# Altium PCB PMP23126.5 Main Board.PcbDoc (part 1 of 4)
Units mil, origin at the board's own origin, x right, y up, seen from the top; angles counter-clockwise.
Board outline 7480.32 x 4667 mil, 6 copper layers (Top Layer, Signal Layer 1, Signal Layer 2, Signal Layer 3, Signal Layer 4, Bottom Layer), stack 65.8 mil thick; 166 components, 83 nets, 633 pads, 4418 vias.
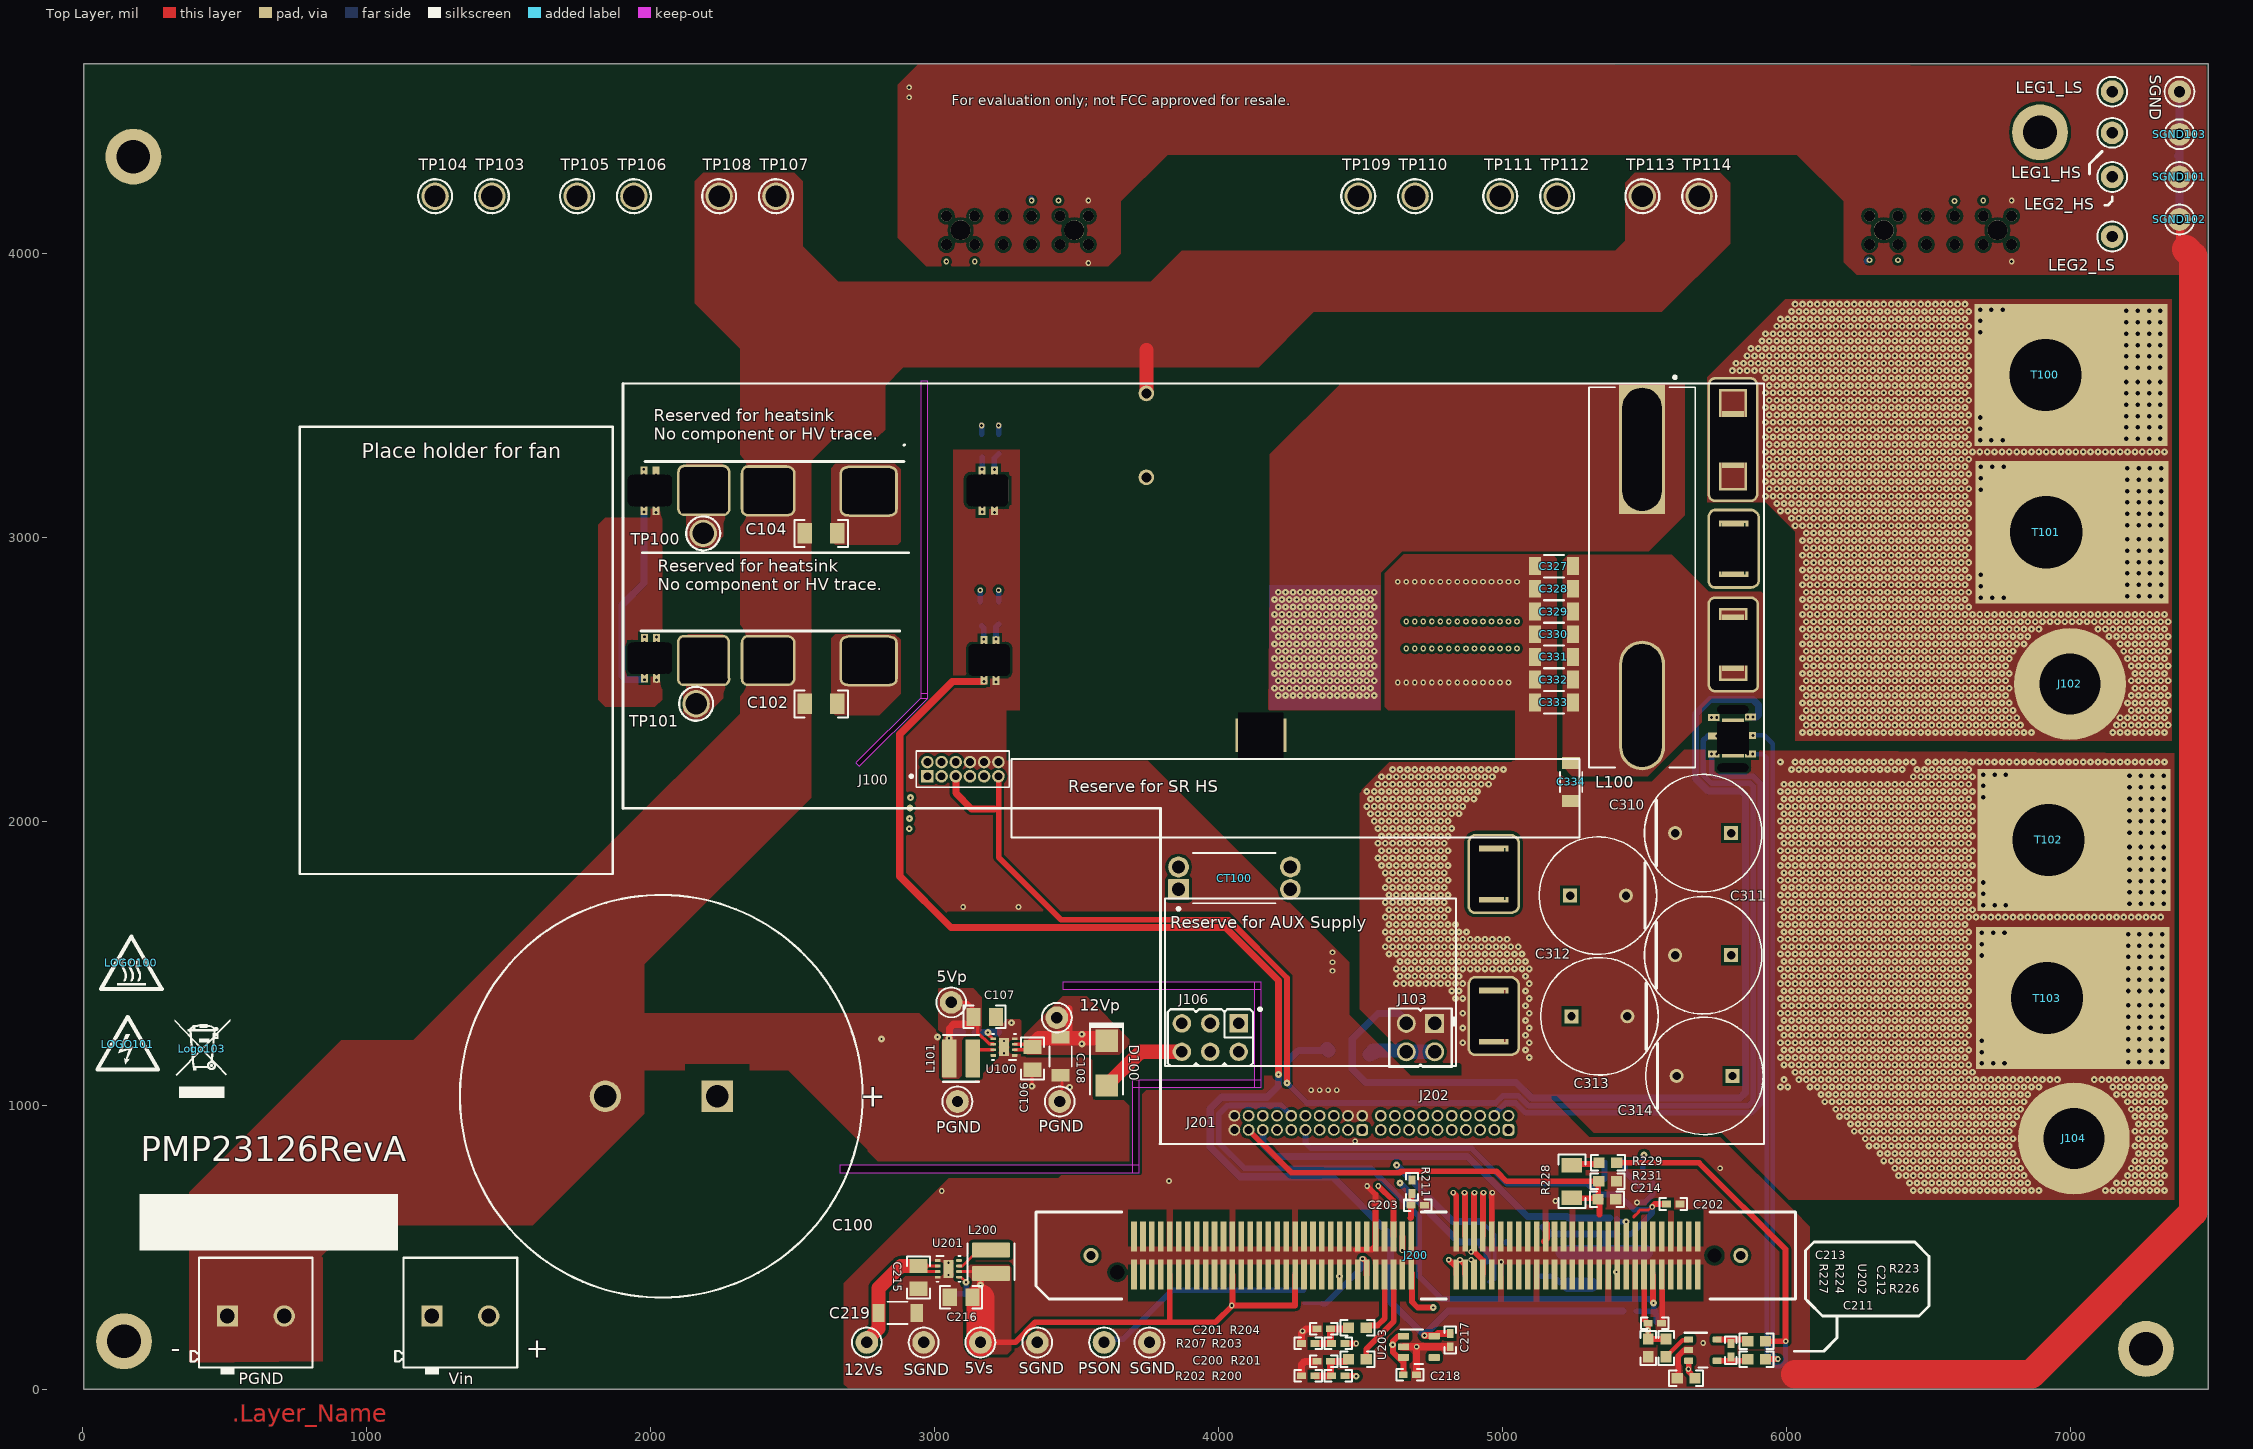
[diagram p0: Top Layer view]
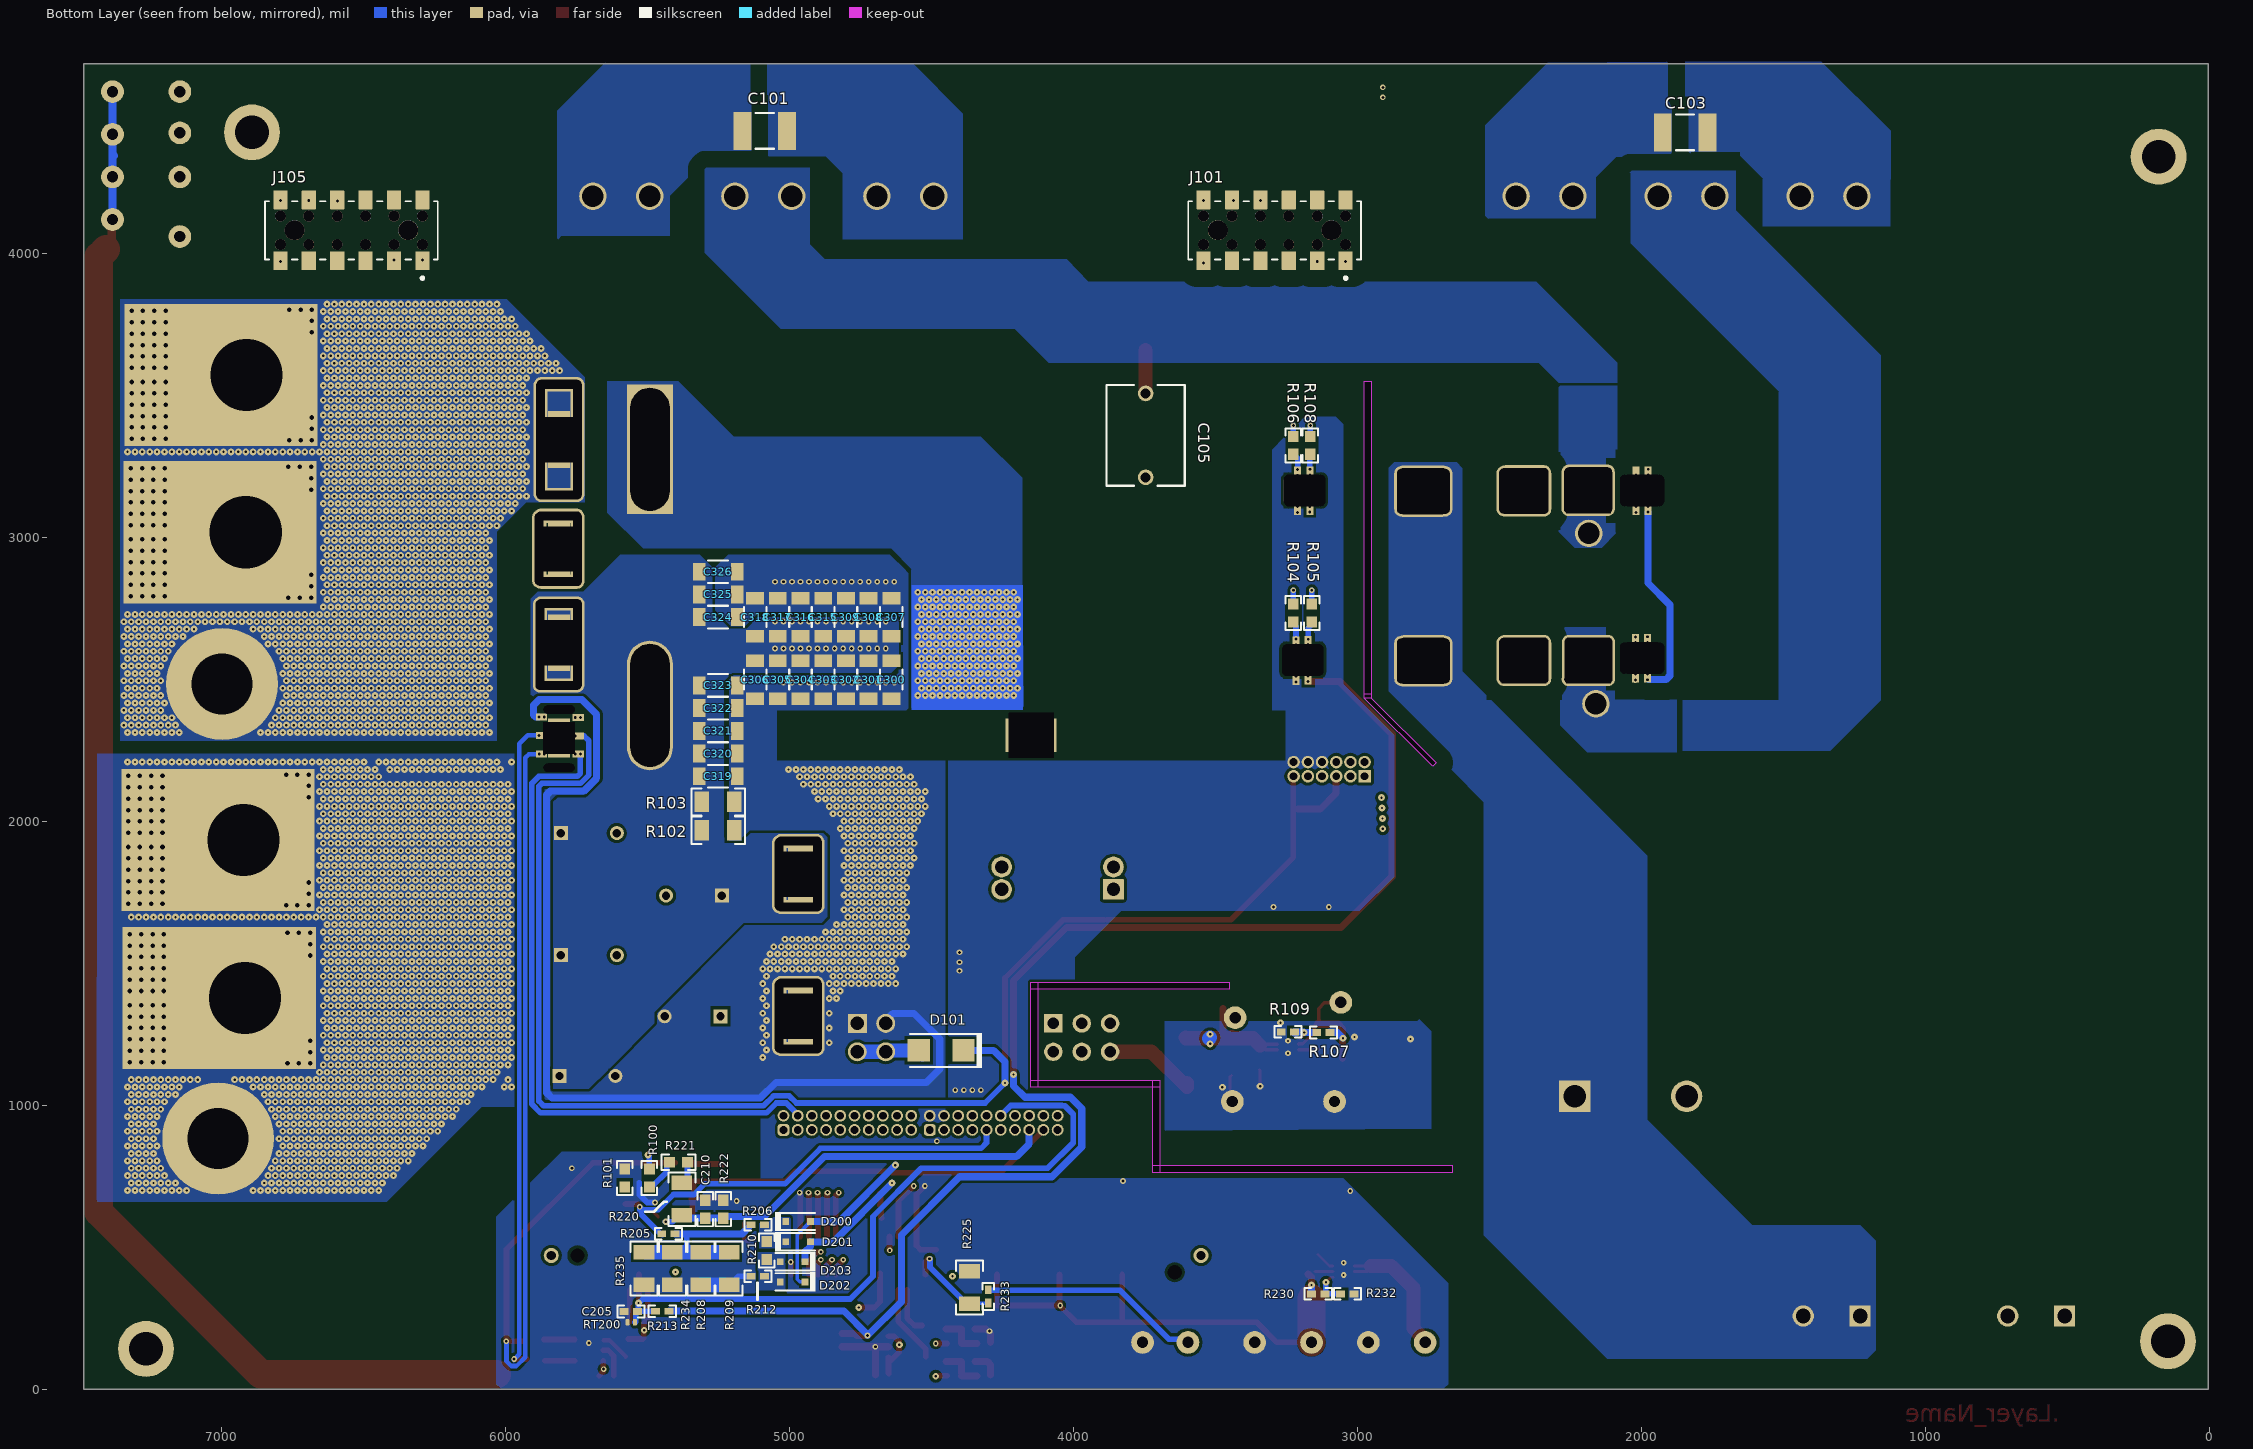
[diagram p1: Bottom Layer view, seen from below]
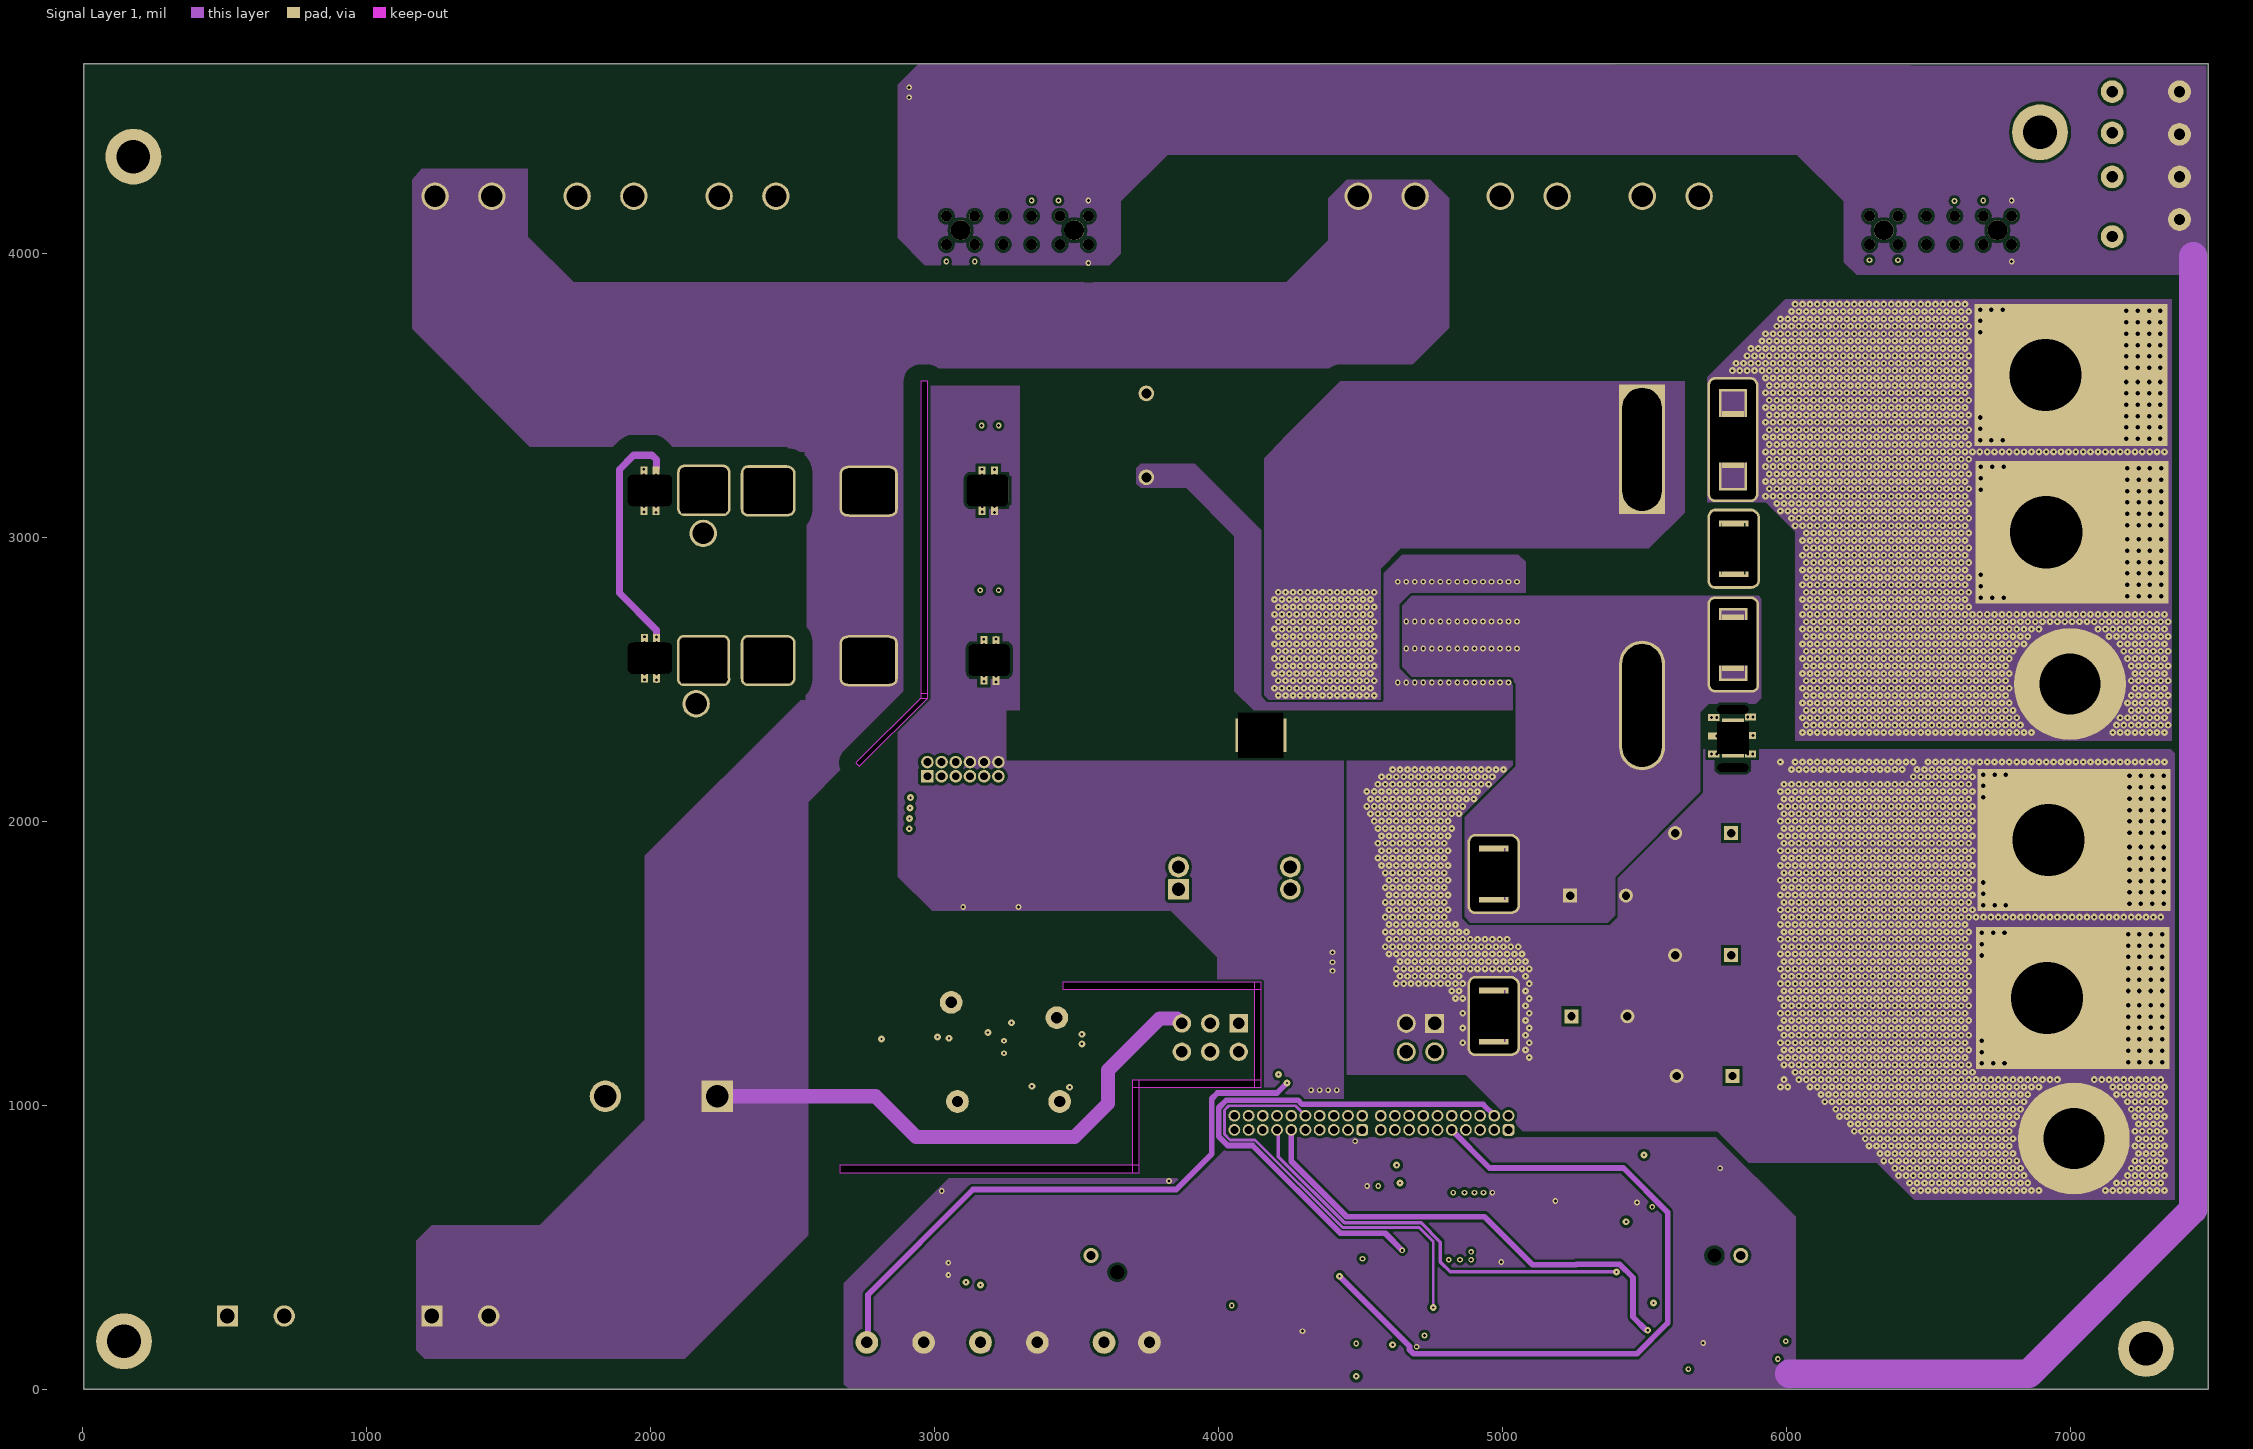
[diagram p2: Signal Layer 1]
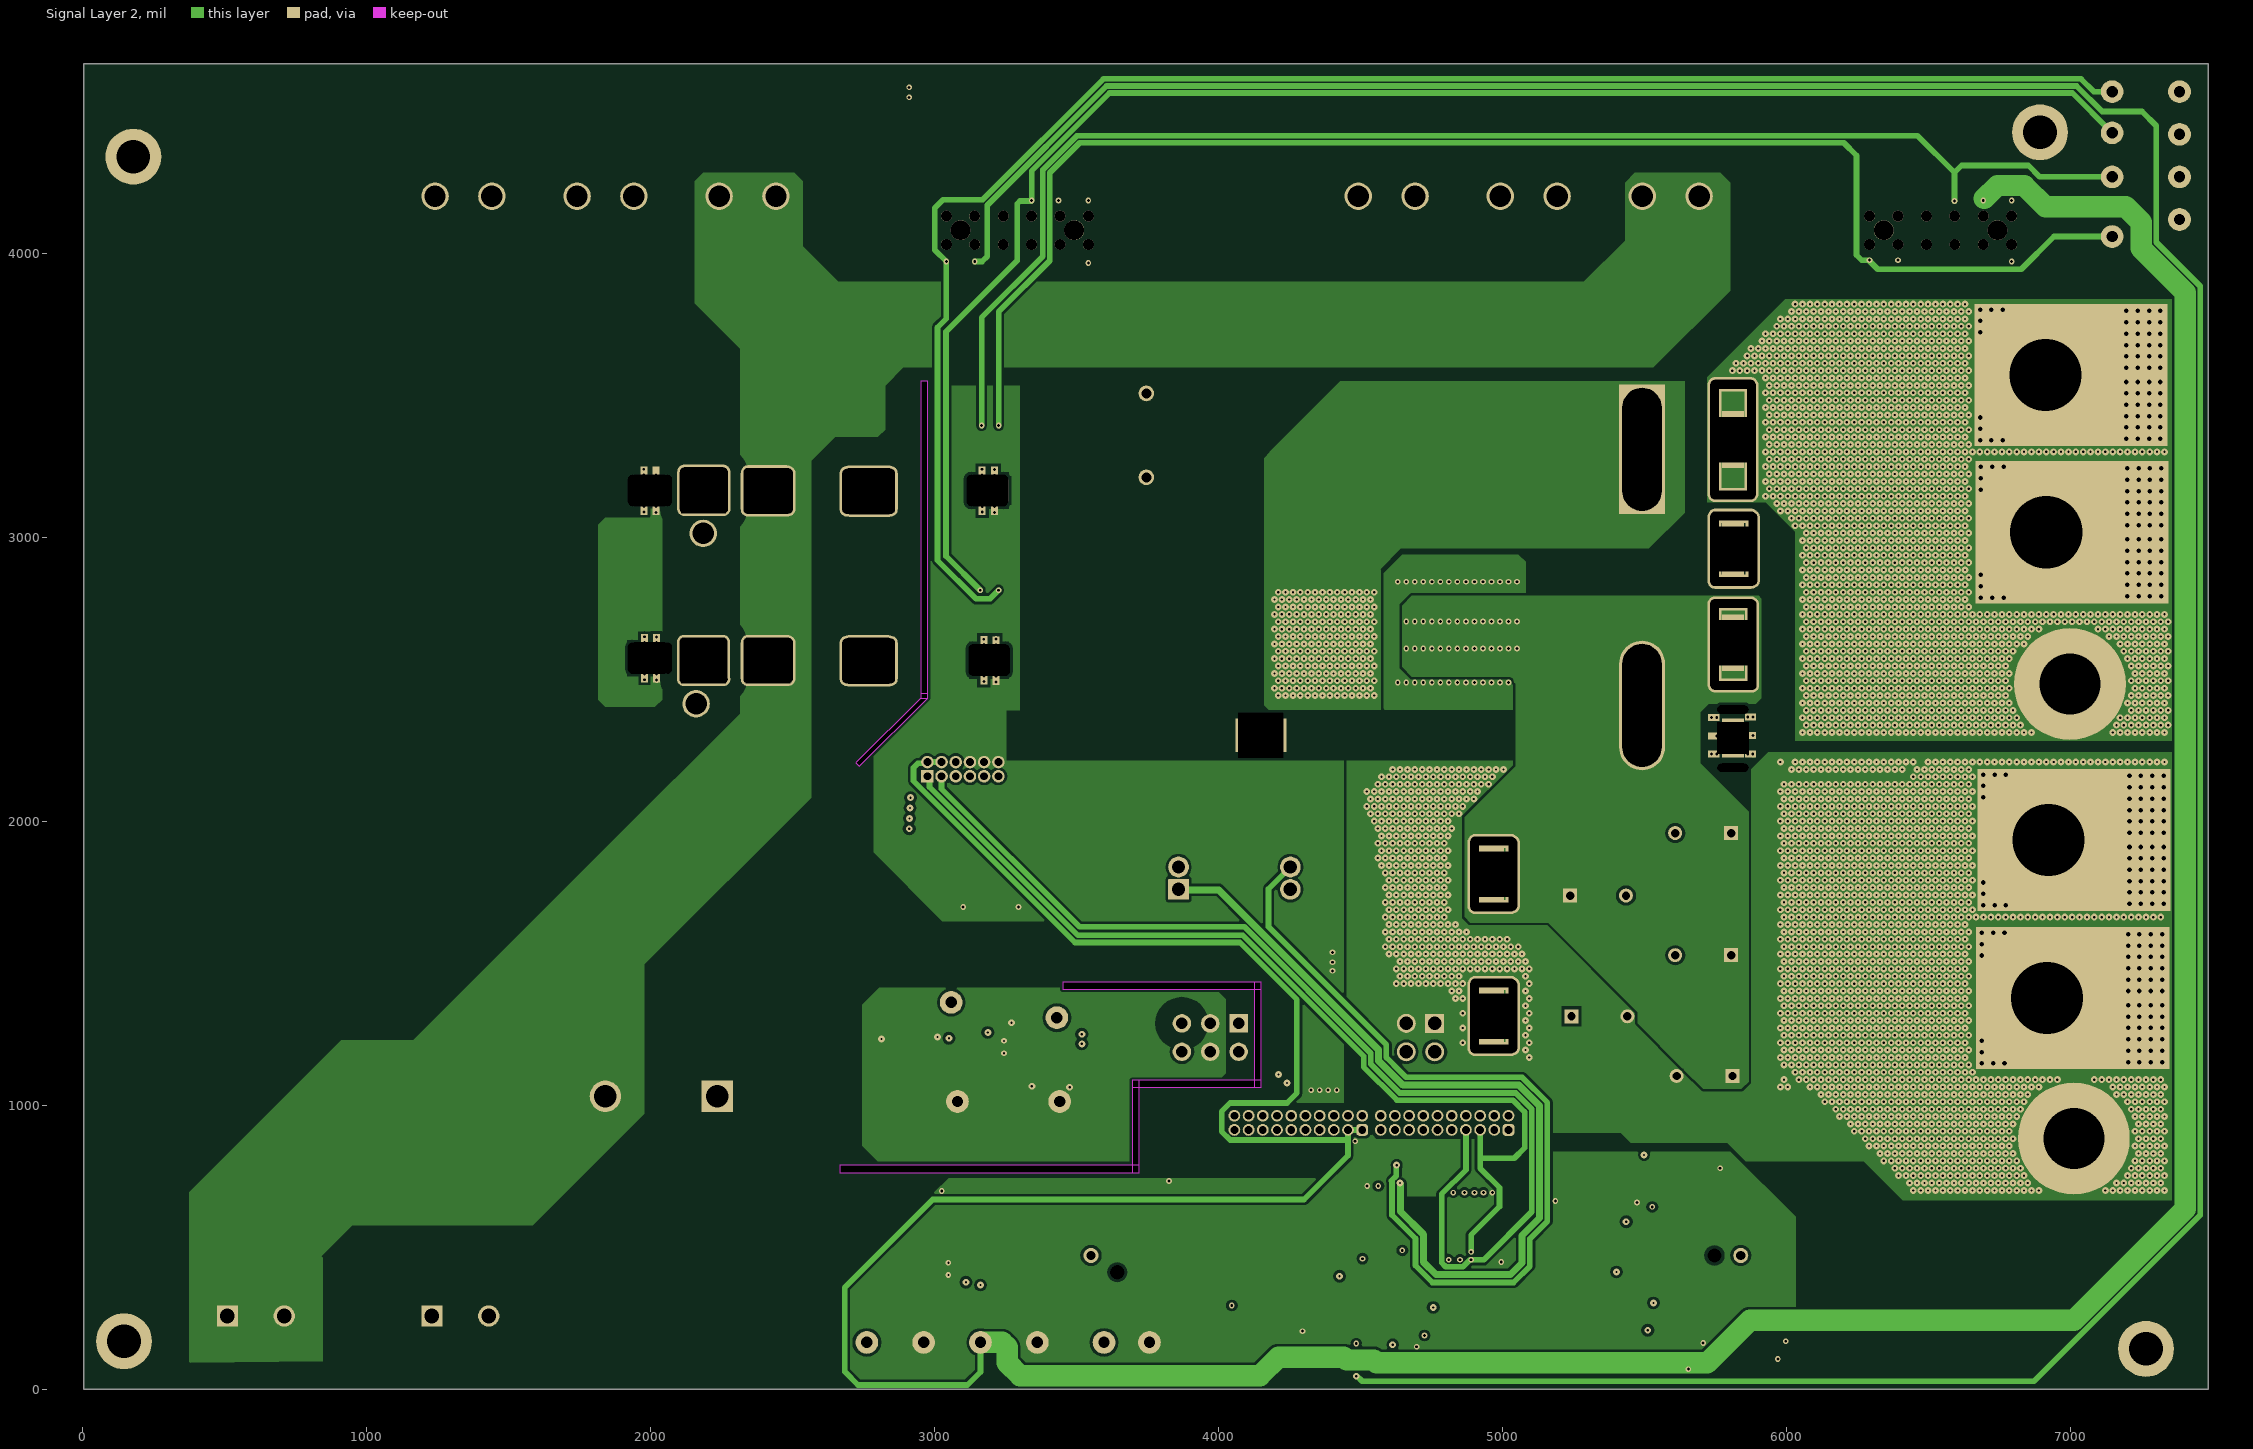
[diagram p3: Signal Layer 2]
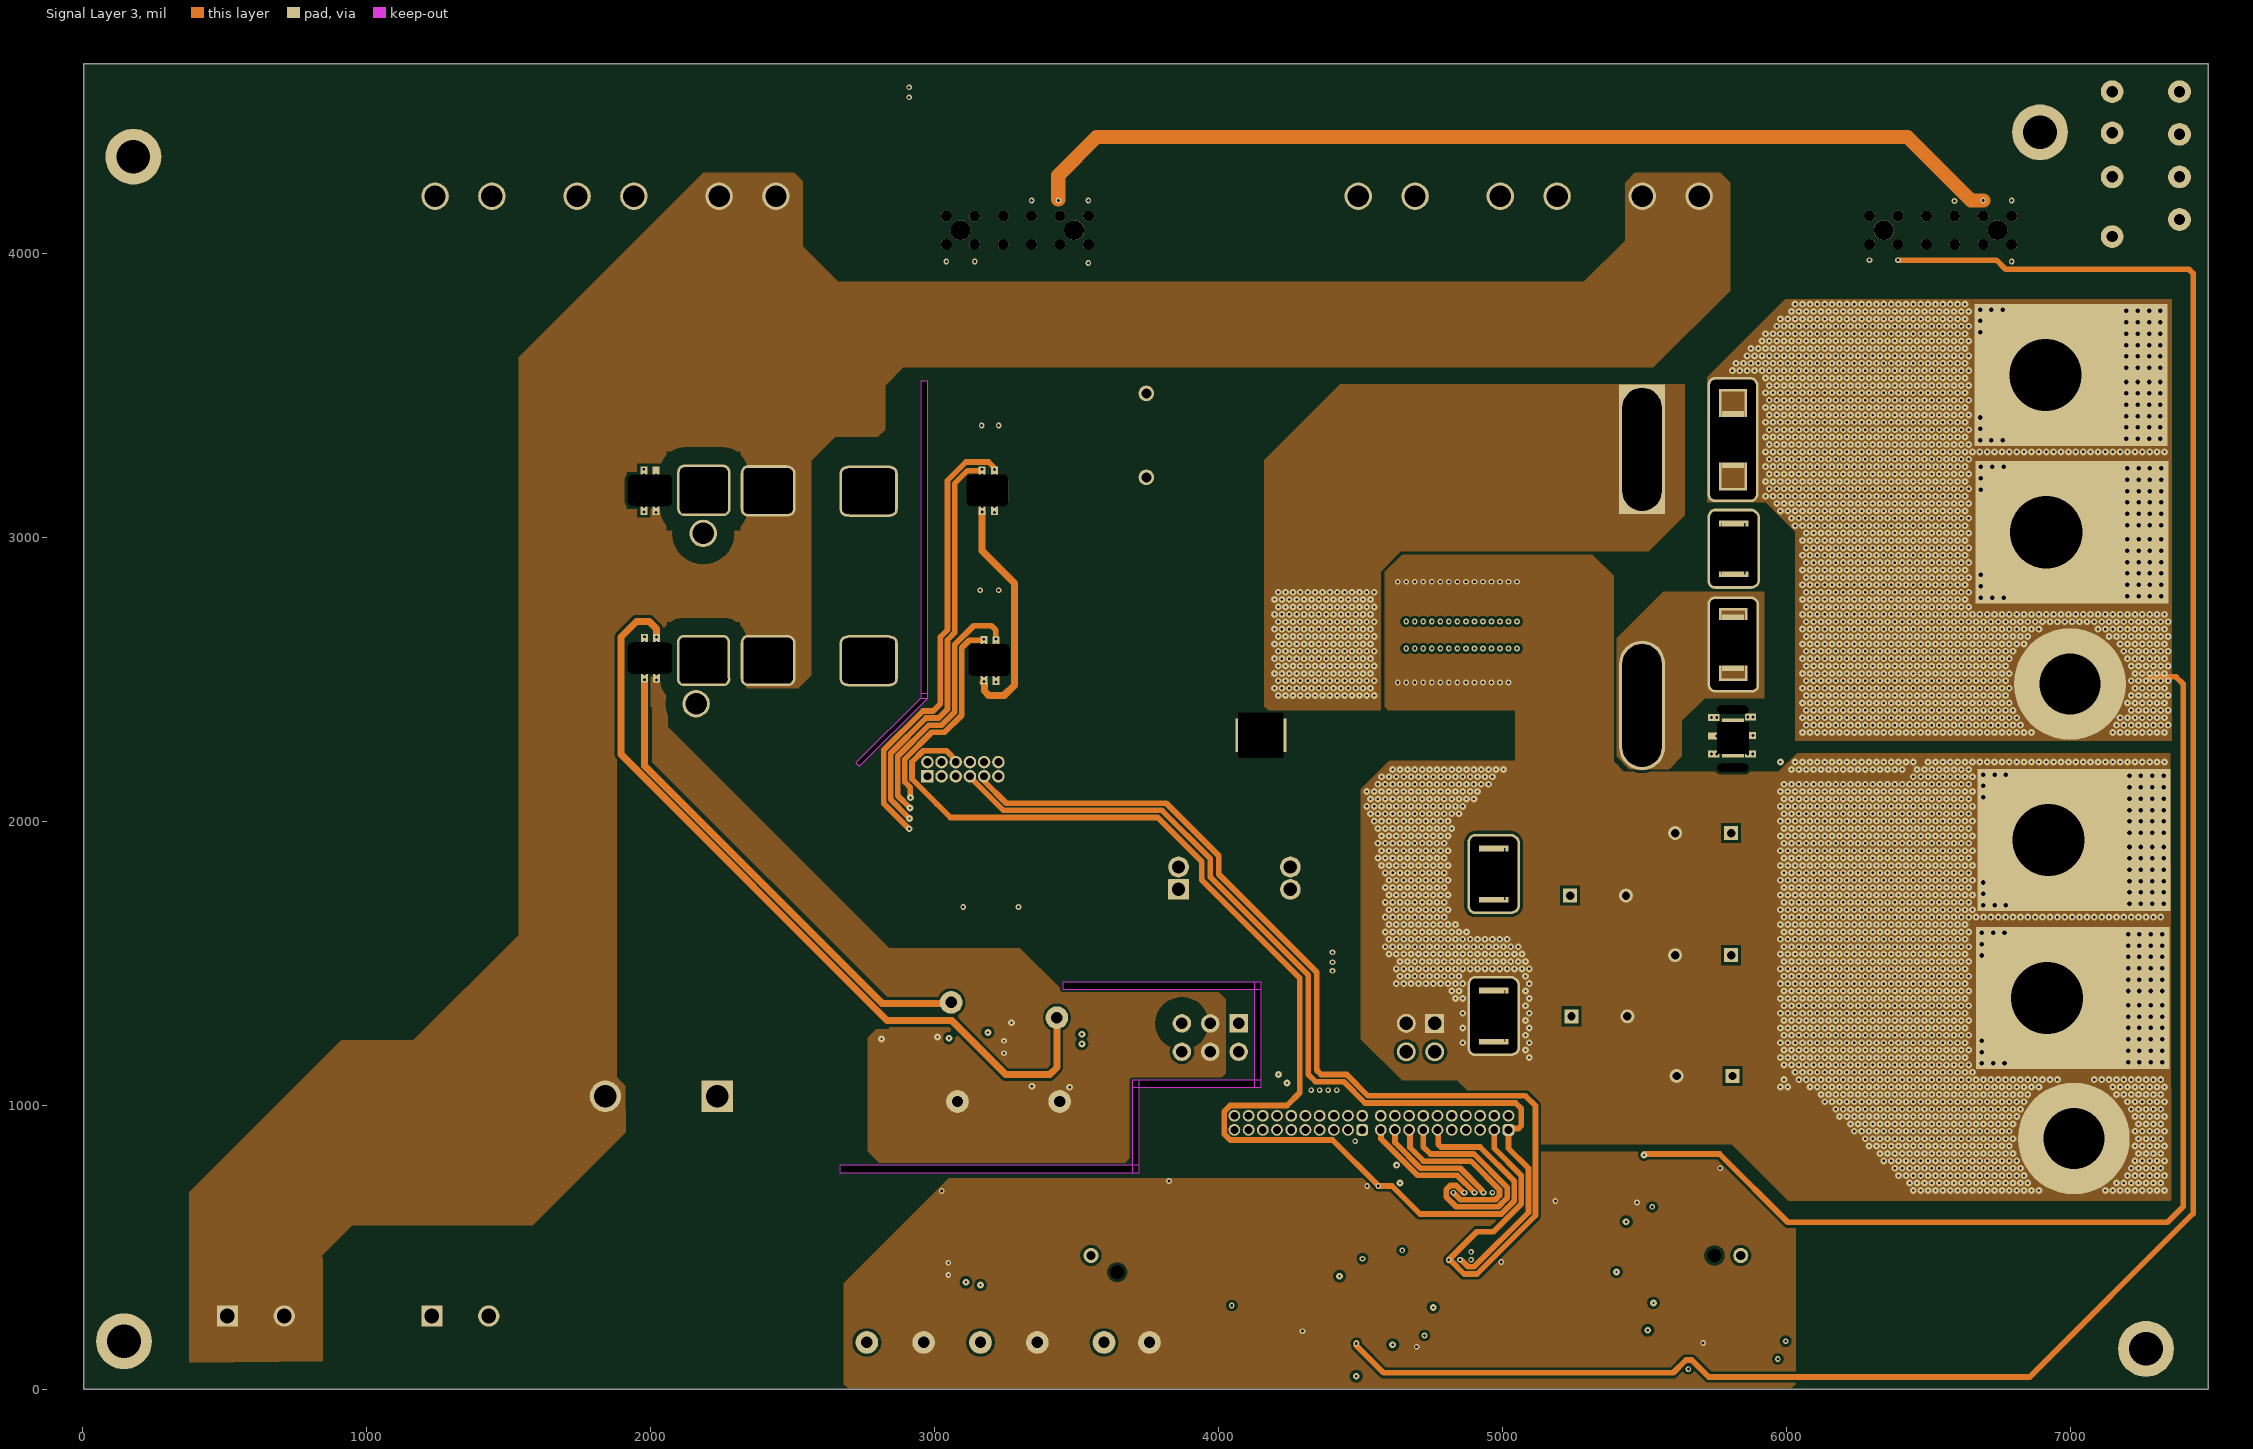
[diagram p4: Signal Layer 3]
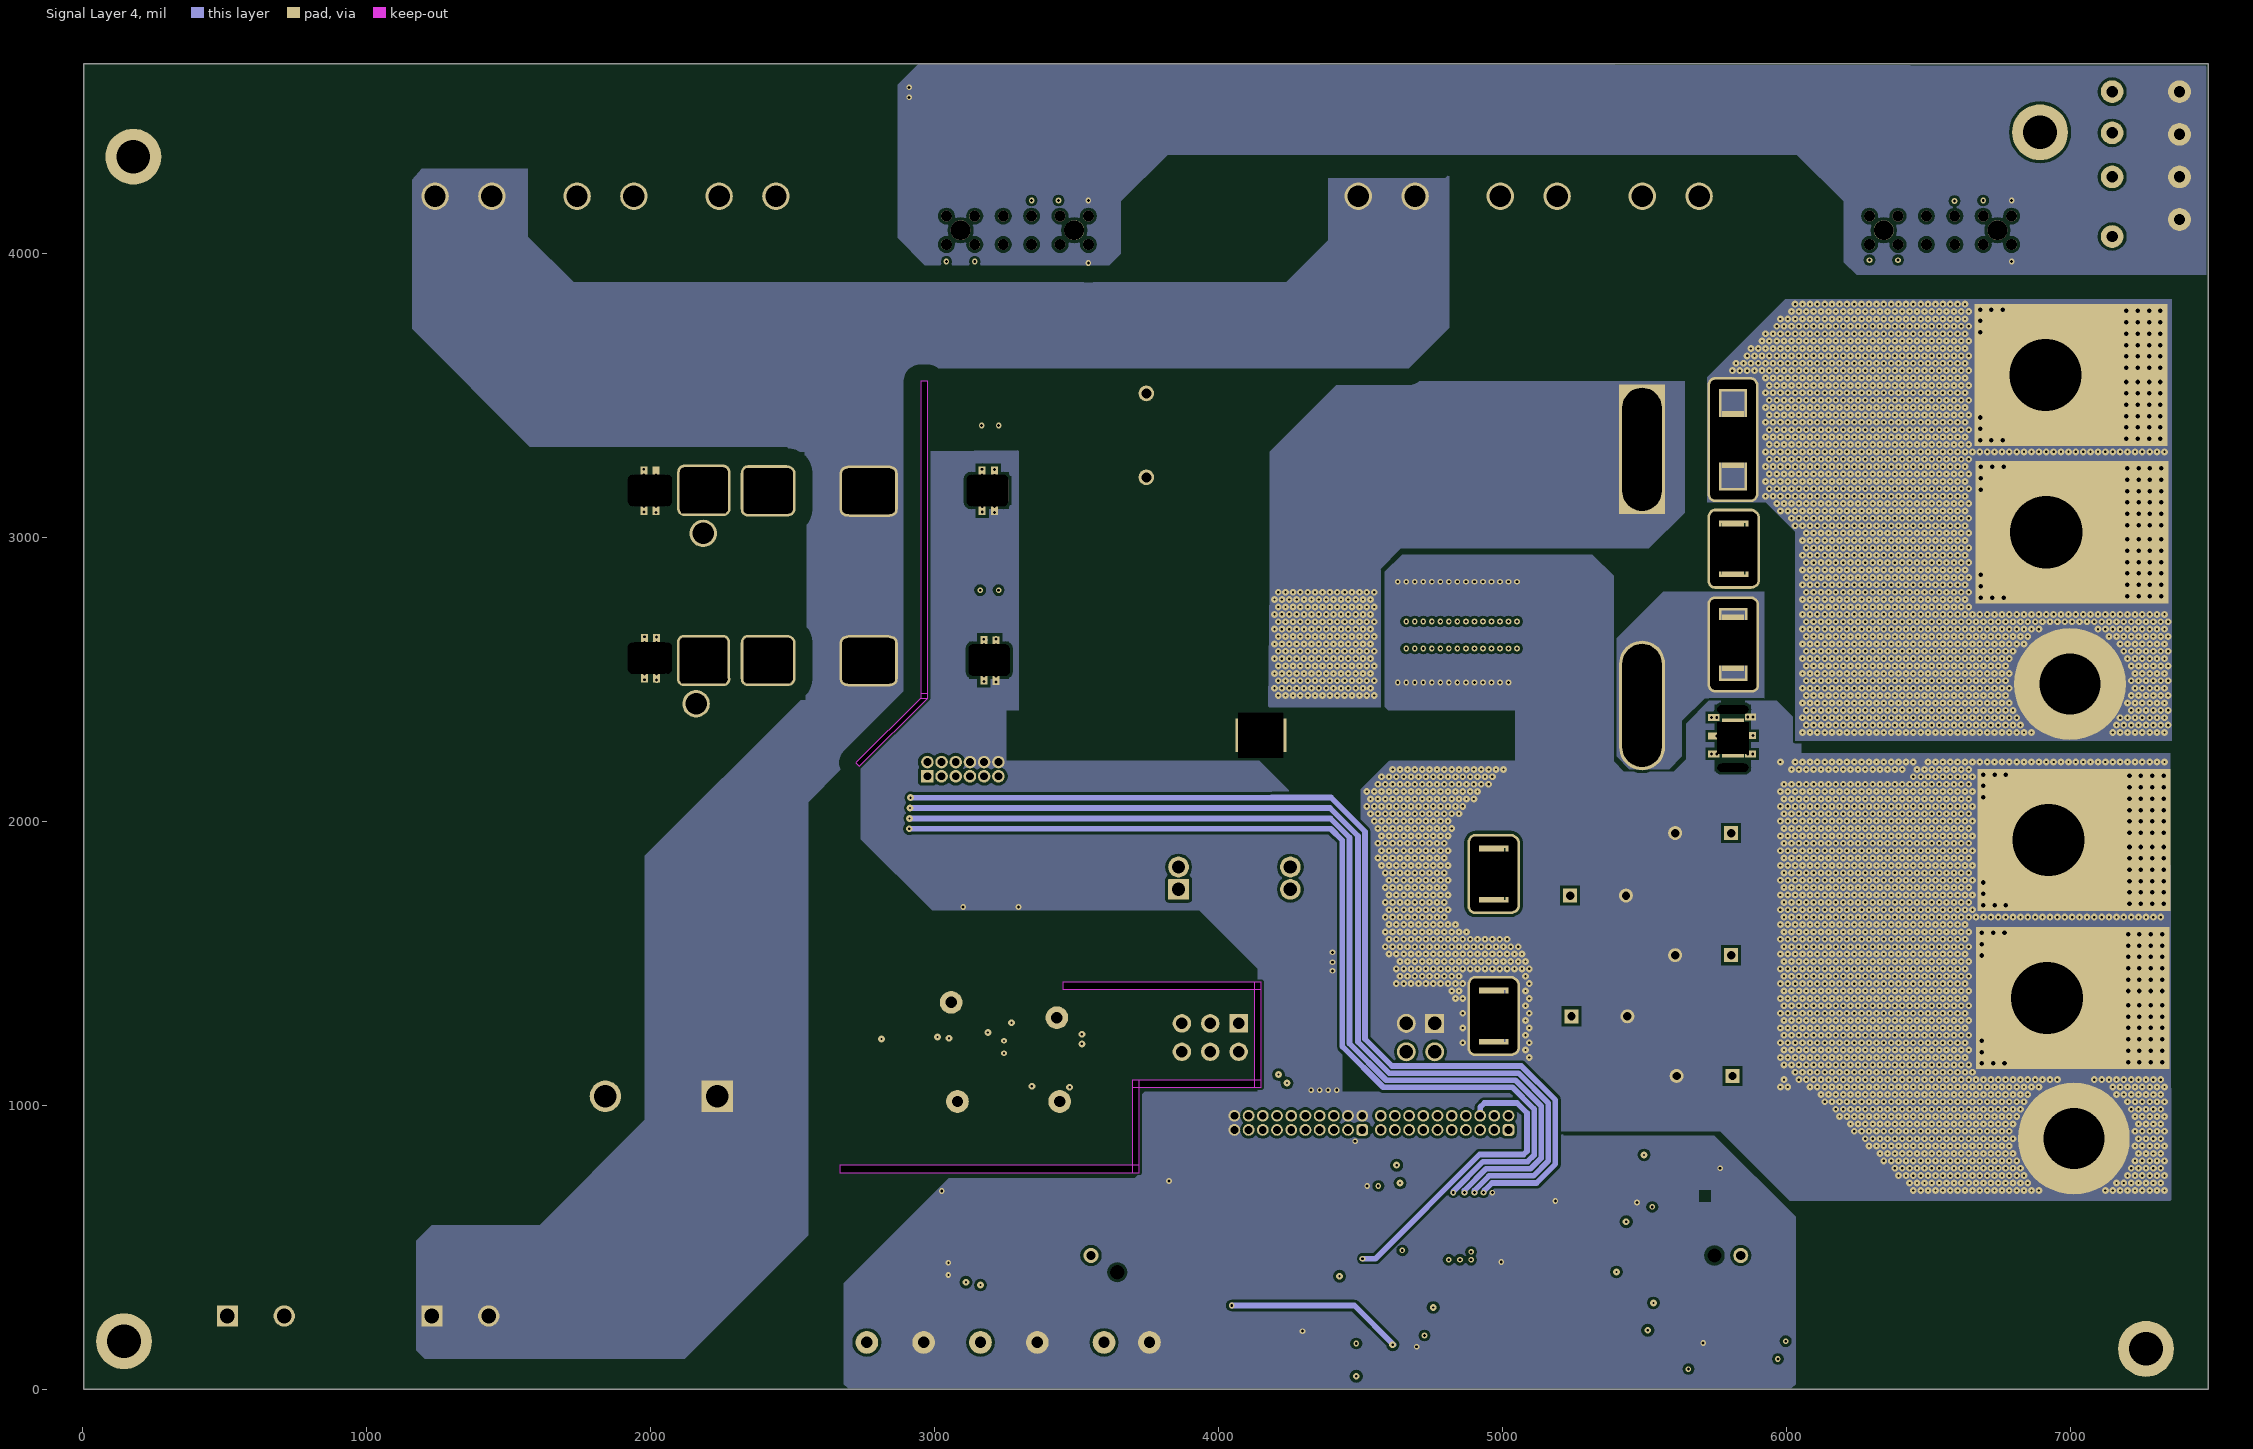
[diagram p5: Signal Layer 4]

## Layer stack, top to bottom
Top Solder: solder mask 0.4, Solder Resist, Dk 3.5
Top Layer: signal copper 2.8
Dielectric 2: prepreg 7, Dk 4.2
Signal Layer 1: signal copper 2.8
Dielectric 3: core 14, Dk 4.2
Signal Layer 2: signal copper 2.8
Dielectric1: prepreg 7, FR-4, Dk 4.2
Signal Layer 3: signal copper 2.8
Dielectric 4: core 14, Dk 4.2
Signal Layer 4: signal copper 2.8
Dielectric 5: prepreg 7, Dk 4.2
Bottom Layer: signal copper 2.8
Bottom Solder: solder mask 0.4, Solder Resist, Dk 3.5

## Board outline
3.6,2 7483.91,2 7483.91,4669 5,4669
cut-out: 4150,1090 3695,1090 3695,1065 4150,1065
cut-out: 3695,1090 3695,765 3720,765 3720,1090
cut-out: 3720,790 2665,790 2665,765 3720,765
cut-out: 4125,1435 4125,1065 4150,1065 4150,1435
cut-out: 4150,1435 3450,1435 3450,1410 4150,1410
cut-out: 2950,2435 2722.5,2207.5 2735,2195 2975,2435 2975,2450 2950,2450
cut-out: 2975,2435 2975,3550 2950,3550 2950,2435

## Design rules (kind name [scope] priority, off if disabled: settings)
AcuteAngle [All] p1: minimum=4.50000000000000E+0001 checktracksonly=FALSE
AssemblyTestPointUsage [All] p1: valid=2
Clearance Clearance_2 [InNetClass('HV') vs Not InNetClass('HV')] p1: gap=60 ignorepadtopadclearanceinfootprint=TRUE except(0: Arc-Hole Track-Hole SMDPad-Hole THPad-Hole Via-Hole Fill-Hole Poly-Hole Region-Hole Text-Hole)
Clearance Clearance_1 [InNetClass('MV') vs Not InNetClass('MV')] p2: gap=40 ignorepadtopadclearanceinfootprint=TRUE
Clearance Clearance_Keepouts [((IsTrack Or IsArc) And Not InPoly) And IsFree and IsKeepOut vs ((IsTrack Or IsArc) And Not InPoly) And IsFree and IsKeepOut] p3: gap=0 ignorepadtopadclearanceinfootprint=FALSE
Clearance Clearance_BoardEdge_MountingHoles [OnCopper and InComponentClass('Mounting Holes') vs IsKeepOut] p4: gap=40 ignorepadtopadclearanceinfootprint=FALSE except(0: Arc-Hole Track-Hole SMDPad-Hole THPad-Hole Via-Hole Fill-Hole Poly-Hole Region-Hole Text-Hole)
Clearance Clearance_BoardEdge_Poly [OnCopper and InPoly vs IsKeepOut] p5: gap=25 ignorepadtopadclearanceinfootprint=FALSE except(0: Arc-Hole Track-Hole SMDPad-Hole THPad-Hole Via-Hole Fill-Hole Poly-Hole Region-Hole Text-Hole)
Clearance Clearance_BoardEdge [OnCopper and Not InComponentClass('Logo') and not InComponentClass('FiducialMark') and not InRegion(1000,500,4000,800) and Not IsKeepout vs IsKeepOut] p6: gap=75 ignorepadtopadclearanceinfootprint=FALSE except(0: Arc-Hole Track-Hole SMDPad-Hole THPad-Hole Via-Hole Fill-Hole Poly-Hole Region-Hole Text-Hole)
Clearance Clearance_Poly [InPolygon] p7: gap=10 ignorepadtopadclearanceinfootprint=FALSE except(0: Arc-Hole Track-Hole SMDPad-Hole THPad-Hole Via-Hole Fill-Hole Poly-Hole Region-Hole Text-Hole)
Clearance [All] p8: gap=7.87 ignorepadtopadclearanceinfootprint=FALSE except(0: Arc-SMDPad Arc-Hole Track-Hole SMDPad-Hole THPad-Hole Via-Hole Fill-Hole Poly-Hole Region-Hole Text-Hole; 5: Arc-Arc Arc-Track Arc-THPad Arc-Via Arc-Fill Track-Track Track-SMDPad Track-THPad Track-Via Track-Fill SMDPad-SMDPad SMDPad-THPad SMDPad-Via SMDPad-Fill THPad-THPad THPad-Via THPad-Fill Via-Via Via-Fill Fill-Fill)
ComponentClearance ComponentClearance_MountingHoles_FiducialMarks [InComponentClass('Mounting Holes') vs InComponentClass('FiducialMark')] p1: gap=20 collisioncheckmode=3 verticalgap=7 showdistances=FALSE
ComponentClearance ComponentClearance_Shunt [InComponentClass('Header') vs InComponentClass('Shunt')] p2: gap=0 collisioncheckmode=3 verticalgap=0 showdistances=FALSE
ComponentClearance ComponentClearance_Logo [InComponentClass('Logo')] p3: gap=5 collisioncheckmode=3 verticalgap=10 showdistances=FALSE
ComponentClearance ComponentClearance_ScrewToNut [(HasFootprint('KEYSTONE_4824')) vs (HasFootprint('Keystone_1903C'))] p4: gap=0 collisioncheckmode=3 verticalgap=0 showdistances=FALSE
ComponentClearance ComponentClearance_MountingHoles [InComponentClass('Mounting Holes')] p5: gap=20 collisioncheckmode=3 verticalgap=7 showdistances=FALSE
ComponentClearance ComponentClearance_SmallPassives [HasFootprint('0201*') or HasFootprint('0402*') or HasFootprint('0508') or HasFootprint('0603*') or HasFootprint('0612') or HasFootprint('0805*') or HasFootprint('0815*') or HasFootprint('0830*') or HasFootprint('1206*') or HasFootprint('1210*') or HasFootprint('1808*') or HasFootprint('1812*') or HasFootprint('1825*') or HasFootprint('2010*') or HasFootprint('2220*') or HasFootprint('2225*') or HasFootprint('2512*') or HasFootprint('2728*') or HasFootprint('3518*') vs HasFootprint('0201*') or HasFootprint('0402*') or HasFootprint('0508') or HasFootprint('0603*') or HasFootprint('0612') or HasFootprint('0805*') or HasFootprint('0815*') or HasFootprint('0830*') or HasFootprint('1206*') or HasFootprint('1210*') or HasFootprint('1808*') or HasFootprint('1812*') or HasFootprint('1825*') or HasFootprint('2010*') or HasFootprint('2220*') or HasFootprint('2225*') or HasFootprint('2512*') or HasFootprint('2728*') or HasFootprint('3518*')] p6: gap=5 collisioncheckmode=3 verticalgap=1 showdistances=FALSE
ComponentClearance ComponentClearance_THtoSMT [IsThruComponent vs IsSMTComponent] p7: gap=10 collisioncheckmode=3 verticalgap=7 showdistances=FALSE
ComponentClearance ComponentClearance_THtoTH [IsThruComponent vs IsThruComponent] p8: gap=10 collisioncheckmode=3 verticalgap=7 showdistances=FALSE
ComponentClearance [All] p9: gap=10 collisioncheckmode=3 verticalgap=7 showdistances=FALSE
DiffPairsRouting [All] p1: maxlimit=100 minlimit=10 mostfreqgap=10 toplayer_minwidth=15 toplayer_maxwidth=15 toplayer_prefwidth=15 midlayer1_minwidth=15 midlayer1_maxwidth=15 midlayer1_prefwidth=15 midlayer2_minwidth=15 midlayer2_maxwidth=15 midlayer2_prefwidth=15 midlayer3_minwidth=15 midlayer3_maxwidth=15 midlayer3_prefwidth=15 midlayer4_minwidth=15 midlayer4_maxwidth=15 midlayer4_prefwidth=15 bottomlayer_minwidth=15 bottomlayer_maxwidth=15 bottomlayer_prefwidth=15 maxuncoupledlength=1000
FabricationTestPointUsage TestPointUsage [All] p1: valid=2 allowmultiple=FALSE
FabricationTestpoint Testpoint [All] p1: side=3 testpointundercomponent=TRUE minsize=40 maxsize=100 preferedsize=60 minholesize=0 maxholesize=40 preferedholesize=32 testpointgrid=1 allowsidetop=TRUE allowsidebottom=TRUE usegrid=TRUE gridtolerance=0.01
FanoutControl Fanout_LCC [IsLCC] p1: bgadir=Out bgaviamode=Centered fanoutstyle=Auto fanoutdirection=Alternating viagrid=1 // Fanout_LCC (Default Rule)
FanoutControl Fanout_BGA [IsBGA] p2: bgadir=Out bgaviamode=Centered fanoutstyle=Auto fanoutdirection=Alternating viagrid=1 // Fanout_BGA (Default Rule)
FanoutControl Fanout_Default [All] p4: bgadir=Out bgaviamode=Centered fanoutstyle=Auto fanoutdirection=Alternating viagrid=1 // Fanout_Default (Default Rule)
FanoutControl Fanout_Small [(CompPinCount < 5)] p5: bgadir=Out bgaviamode=Centered fanoutstyle=Auto fanoutdirection=OutThenIn viagrid=1 // Fanout_Small (Default Rule)
Height [All] p1: minheight=0 maxheight=3000 prefheight=500
HoleSize [All] p1: absolutevalues=TRUE maxlimit=501 minlimit=7 maxpercent=80.000 minpercent=20.000
MinimumAnnularRing MinimumAnnularRing_ThermalPadVias [IsVia and InAnyComponent] p1: minimumring=5.91
MinimumAnnularRing [All] p2: minimumring=5
MinimumSolderMaskSliver MinimumSolderMaskSliver_Logo [InComponentClass('Logo') vs InComponentClass('Logo')] p1: minsoldermaskwidth=0.7
MinimumSolderMaskSliver [All] p2: minsoldermaskwidth=0.7
PlaneConnect [All] p1: planeconnectstyle=Direct reliefexpansion=10 reliefentries=4 reliefconductorwidth=10 reliefairgap=10
PolygonConnect PolygonConnect_16 [All vs IsNamedPolygon('C106_2') Or  IsNamedPolygon('Vout') Or  IsNamedPolygon('IN+') Or  IsNamedPolygon('Q203_5') Or  IsNamedPolygon('IN+') Or  IsNamedPolygon('Q201_5') Or  IsNamedPolygon('C108_2') Or  IsNamedPolygon('SGND') Or  IsNamedPolygon('IN+') Or  IsNamedPolygon('SGND') Or  IsNamedPolygon('Q203_5') Or  IsNamedPolygon('IN+') Or  IsNamedPolygon('SGND') Or  IsNamedPolygon('GND') Or  IsNamedPolygon('C113_2') Or  IsNamedPolygon('C107_2') Or  IsNamedPolygon('C107_2') Or  IsNamedPolygon('Vout') Or  IsNamedPolygon('SIGNAL_LAYER_1_GND_P074') Or  IsNamedPolygon('HV') Or  IsNamedPolygon('C108_2') Or  IsNamedPolygon('C103_2') Or  IsNamedPolygon('Q201_5') Or  IsNamedPolygon('Vout') Or  IsNamedPolygon('C109_2') Or  IsNamedPolygon('Q201_5') Or  IsNamedPolygon('GND') Or  IsNamedPolygon('C107_2') Or  IsNamedPolygon('C102_1') Or  IsNamedPolygon('GND') Or  IsNamedPolygon('SGND') Or  IsNamedPolygon('HS') Or  IsNamedPolygon('Q203_5') Or  IsNamedPolygon('Q201_5') Or  IsNamedPolygon('Q203_5')] p1: connectstyle=Direct reliefconductorwidth=10 reliefentries=4 polygonreliefangle="90 Angle" airgapwidth=10
PolygonConnect PolygonConnect_15 [All vs IsNamedPolygon('C109_2') Or  IsNamedPolygon('C107_2') Or  IsNamedPolygon('HV') Or  IsNamedPolygon('Q203_5') Or  IsNamedPolygon('C107_2') Or  IsNamedPolygon('HS') Or  IsNamedPolygon('Q201_5') Or  IsNamedPolygon('Q203_5') Or  IsNamedPolygon('C106_2') Or  IsNamedPolygon('C108_2') Or  IsNamedPolygon('Vout') Or  IsNamedPolygon('Q203_5') Or  IsNamedPolygon('C108_2') Or  IsNamedPolygon('C113_2') Or  IsNamedPolygon('Q203_5') Or  IsNamedPolygon('Q201_5') Or  IsNamedPolygon('C107_2') Or  IsNamedPolygon('C102_1') Or  IsNamedPolygon('SGND') Or  IsNamedPolygon('GND') Or  IsNamedPolygon('SGND') Or  IsNamedPolygon('GND') Or  IsNamedPolygon('IN+') Or  IsNamedPolygon('IN+') Or  IsNamedPolygon('Q201_5') Or  IsNamedPolygon('Q201_5') Or  IsNamedPolygon('SGND') Or  IsNamedPolygon('SGND') Or  IsNamedPolygon('Vout') Or  IsNamedPolygon('Vout') Or  IsNamedPolygon('IN+') Or  IsNamedPolygon('GND') Or  IsNamedPolygon('IN+') Or  IsNamedPolygon('GND')] p2: connectstyle=Direct reliefconductorwidth=10 reliefentries=4 polygonreliefangle="90 Angle" airgapwidth=10
PolygonConnect PolygonConnect_14 [All vs IsNamedPolygon('C106_2') Or  IsNamedPolygon('C107_2') Or  IsNamedPolygon('C107_2') Or  IsNamedPolygon('C107_2') Or  IsNamedPolygon('C102_1') Or  IsNamedPolygon('Q203_5') Or  IsNamedPolygon('Vout') Or  IsNamedPolygon('Q203_5') Or  IsNamedPolygon('Q203_5') Or  IsNamedPolygon('Q201_5') Or  IsNamedPolygon('C108_2') Or  IsNamedPolygon('Q203_5') Or  IsNamedPolygon('HS') Or  IsNamedPolygon('HV') Or  IsNamedPolygon('C108_2') Or  IsNamedPolygon('Q201_5') Or  IsNamedPolygon('C109_2') Or  IsNamedPolygon('Q201_5') Or  IsNamedPolygon('Q201_5') Or  IsNamedPolygon('C113_2')] p3: connectstyle=Direct reliefconductorwidth=10 reliefentries=4 polygonreliefangle="90 Angle" airgapwidth=10
PolygonConnect PolygonConnect_13 [All vs IsNamedPolygon('C102_1') Or  IsNamedPolygon('HV') Or  IsNamedPolygon('C107_2') Or  IsNamedPolygon('C109_2') Or  IsNamedPolygon('C107_2') Or  IsNamedPolygon('C108_2') Or  IsNamedPolygon('C106_2') Or  IsNamedPolygon('C108_2') Or  IsNamedPolygon('C113_2') Or  IsNamedPolygon('C107_2')] p4: connectstyle=Direct reliefconductorwidth=10 reliefentries=4 polygonreliefangle="90 Angle" airgapwidth=10
PolygonConnect PolygonConnect_12 [All vs IsNamedPolygon('C107_2') Or  IsNamedPolygon('C113_2') Or  IsNamedPolygon('C106_2') Or  IsNamedPolygon('C107_2') Or  IsNamedPolygon('C107_2') Or  IsNamedPolygon('C102_1')] p5: connectstyle=Direct reliefconductorwidth=10 reliefentries=4 polygonreliefangle="90 Angle" airgapwidth=10
PolygonConnect PolygonConnect_11 [All vs IsNamedPolygon('C106_2') Or  IsNamedPolygon('C102_1') Or  IsNamedPolygon('C107_2') Or  IsNamedPolygon('C107_2') Or  IsNamedPolygon('C107_2')] p6: connectstyle=Direct reliefconductorwidth=10 reliefentries=4 polygonreliefangle="90 Angle" airgapwidth=10
PolygonConnect PolygonConnect_10 [All vs IsNamedPolygon('C106_2')] p7: connectstyle=Direct reliefconductorwidth=10 reliefentries=4 polygonreliefangle="90 Angle" airgapwidth=10
PolygonConnect PolygonConnect_9 [All vs IsNamedPolygon('C11_1') Or  IsNamedPolygon('Vin') Or  IsNamedPolygon('Vin') Or  IsNamedPolygon('5V') Or  IsNamedPolygon('D6_2') Or  IsNamedPolygon('Q3_3') Or  IsNamedPolygon('GND2') Or  IsNamedPolygon('GND2') Or  IsNamedPolygon('GND') Or  IsNamedPolygon('Q3_4') Or  IsNamedPolygon('12V5') Or  IsNamedPolygon('GND') Or  IsNamedPolygon('12V5') Or  IsNamedPolygon('D3_1')] p8: connectstyle=Direct reliefconductorwidth=10 reliefentries=4 polygonreliefangle="90 Angle" airgapwidth=10
PolygonConnect PolygonConnect_8 [All vs IsNamedPolygon('C11_1') Or  IsNamedPolygon('Vin') Or  IsNamedPolygon('12V5') Or  IsNamedPolygon('Q3_3') Or  IsNamedPolygon('GND2') Or  IsNamedPolygon('GND2') Or  IsNamedPolygon('5V') Or  IsNamedPolygon('Q3_4') Or  IsNamedPolygon('12V5')] p9: connectstyle=Direct reliefconductorwidth=10 reliefentries=4 polygonreliefangle="90 Angle" airgapwidth=10
PolygonConnect PolygonConnect_7 [All vs IsNamedPolygon('GND2') Or  IsNamedPolygon('GND2') Or  IsNamedPolygon('5V') Or  IsNamedPolygon('12V5') Or  IsNamedPolygon('12V5') Or  IsNamedPolygon('C11_1')] p10: connectstyle=Direct reliefconductorwidth=10 reliefentries=4 polygonreliefangle="90 Angle" airgapwidth=10
PolygonConnect PolygonConnect_6 [All vs IsNamedPolygon('GND2') Or  IsNamedPolygon('SGND') Or  IsNamedPolygon('GND1') Or  IsNamedPolygon('C901_1') Or  IsNamedPolygon('SGND') Or  IsNamedPolygon('GND2') Or  IsNamedPolygon('GND1')] p11: connectstyle=Direct reliefconductorwidth=10 reliefentries=4 polygonreliefangle="90 Angle" airgapwidth=10
PolygonConnect PolygonConnect_5 [All vs IsNamedPolygon('GND1') Or  IsNamedPolygon('GND1')] p12: connectstyle=Direct reliefconductorwidth=10 reliefentries=4 polygonreliefangle="90 Angle" airgapwidth=10
PolygonConnect PolygonConnect_4 [All vs IsNamedPolygon('C21_1') Or  IsNamedPolygon('C5_1') Or  IsNamedPolygon('C12_2') Or  IsNamedPolygon('C2_2') Or  IsNamedPolygon('C13_1') Or  IsNamedPolygon('C28_1') Or  IsNamedPolygon('C6_1') Or  IsNamedPolygon('GND') Or  IsNamedPolygon('GND2') Or  IsNamedPolygon('C14_1') Or  IsNamedPolygon('C13_1') Or  IsNamedPolygon('Q1_3') Or  IsNamedPolygon('C14_1') Or  IsNamedPolygon('C5_1') Or  IsNamedPolygon('GND2') Or  IsNamedPolygon('C28_1') Or  IsNamedPolygon('D5_2') Or  IsNamedPolygon('D6_2') Or  IsNamedPolygon('D2_1') Or  IsNamedPolygon('C12_2') Or  IsNamedPolygon('D2_1') Or  IsNamedPolygon('C4_1') Or  IsNamedPolygon('C4_1') Or  IsNamedPolygon('C2_2') Or  IsNamedPolygon('GND') Or  IsNamedPolygon('C33_1') Or  IsNamedPolygon('C9_1')] p13: connectstyle=Direct reliefconductorwidth=10 reliefentries=4 polygonreliefangle="90 Angle" airgapwidth=10
PolygonConnect PolygonConnect_3 [All vs IsNamedPolygon('C28_1') Or  IsNamedPolygon('C12_2') Or  IsNamedPolygon('C28_1') Or  IsNamedPolygon('C9_1') Or  IsNamedPolygon('D5_2') Or  IsNamedPolygon('C12_2') Or  IsNamedPolygon('C2_2') Or  IsNamedPolygon('C14_1') Or  IsNamedPolygon('C4_1') Or  IsNamedPolygon('C14_1') Or  IsNamedPolygon('D6_2') Or  IsNamedPolygon('GND2') Or  IsNamedPolygon('Q1_3') Or  IsNamedPolygon('C5_1') Or  IsNamedPolygon('D2_1') Or  IsNamedPolygon('C4_1') Or  IsNamedPolygon('C13_1') Or  IsNamedPolygon('C5_1') Or  IsNamedPolygon('C13_1') Or  IsNamedPolygon('C33_1') Or  IsNamedPolygon('D2_1') Or  IsNamedPolygon('GND') Or  IsNamedPolygon('GND') Or  IsNamedPolygon('GND2') Or  IsNamedPolygon('C2_2') Or  IsNamedPolygon('C6_1') Or  IsNamedPolygon('C21_1')] p14: connectstyle=Direct reliefconductorwidth=10 reliefentries=4 polygonreliefangle="90 Angle" airgapwidth=10
PolygonConnect PolygonConnect_2 [All vs IsNamedPolygon('C21_1') Or  IsNamedPolygon('C4_1') Or  IsNamedPolygon('D5_2') Or  IsNamedPolygon('C5_1') Or  IsNamedPolygon('C14_1') Or  IsNamedPolygon('C13_1') Or  IsNamedPolygon('C4_1') Or  IsNamedPolygon('C33_1') Or  IsNamedPolygon('C12_2') Or  IsNamedPolygon('D2_1') Or  IsNamedPolygon('C2_2') Or  IsNamedPolygon('C28_1') Or  IsNamedPolygon('C12_2') Or  IsNamedPolygon('D2_1') Or  IsNamedPolygon('C5_1') Or  IsNamedPolygon('Q1_3') Or  IsNamedPolygon('GND') Or  IsNamedPolygon('D6_2') Or  IsNamedPolygon('C6_1') Or  IsNamedPolygon('C2_2') Or  IsNamedPolygon('C14_1') Or  IsNamedPolygon('C28_1') Or  IsNamedPolygon('C13_1') Or  IsNamedPolygon('C9_1') Or  IsNamedPolygon('GND')] p15: connectstyle=Direct reliefconductorwidth=10 reliefentries=4 polygonreliefangle="90 Angle" airgapwidth=10
PolygonConnect PolygonConnect_1 [All vs IsNamedPolygon('C28_1') Or  IsNamedPolygon('D5_2') Or  IsNamedPolygon('C5_1') Or  IsNamedPolygon('C5_1') Or  IsNamedPolygon('D2_1') Or  IsNamedPolygon('C21_1') Or  IsNamedPolygon('C9_1') Or  IsNamedPolygon('C4_1') Or  IsNamedPolygon('C14_1') Or  IsNamedPolygon('C28_1') Or  IsNamedPolygon('C6_1') Or  IsNamedPolygon('C12_2') Or  IsNamedPolygon('C33_1') Or  IsNamedPolygon('C4_1') Or  IsNamedPolygon('C13_1') Or  IsNamedPolygon('C12_2') Or  IsNamedPolygon('D6_2') Or  IsNamedPolygon('C2_2') Or  IsNamedPolygon('C14_1') Or  IsNamedPolygon('D2_1') Or  IsNamedPolygon('C2_2') Or  IsNamedPolygon('C13_1')] p16: connectstyle=Direct reliefconductorwidth=10 reliefentries=4 polygonreliefangle="90 Angle" airgapwidth=10
PolygonConnect [All] p17: connectstyle=Direct reliefconductorwidth=10 reliefentries=4 polygonreliefangle="90 Angle" airgapwidth=10
RoutingVias ThermalPadVias [IsVia and not InNet('SGND')and not InNet('Vout')] p1: holewidth=7.87 width=19.68 viastyle="Through Hole" minholewidth=7.87 minwidth=19.68 maxholewidth=17 maxwidth=35
RoutingVias [IsVia and not InNet('SGND')and not InNet('Vout')] p2: holewidth=16 width=34 viastyle="Through Hole" minholewidth=7.87 minwidth=20 maxholewidth=40 maxwidth=65
SilkToBoardRegionClearance [Not ((IsComment or IsDesignator) And (Hide <> 'False')) and not InRegion(1000,500,4000,800)] p1:
SilkToSilkClearance SilkToSilkClearance_Pb-FreeLogo [(HasFootprint('Pb-Free_Overlay_Medium') OR HasFootprint('Pb-Free_Overlay_Small')) vs (HasFootprint('Pb-Free_Overlay_Medium') OR HasFootprint('Pb-Free_Overlay_Small'))] p1: silktosilkclearance=0
SilkToSilkClearance [All] p2: silktosilkclearance=0
SilkToSolderMaskClearance "Silk to Solder Mask Opening" [All] p1: minsilkscreentomaskgap=0 clearancetoexposedcopper=FALSE
SolderMaskExpansion [All] p1: expansion=1.97 istentingtop=FALSE
UnpouredPolygon [All] p1: allowunpoured=TRUE allowshelved=TRUE
Width [All] p1: maxlimit=100 minlimit=6 preferedwidth=10 checkconnectedcopper=TRUE
13 further rules are at their usual default settings.

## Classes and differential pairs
component class Header: J103 J106
component class PMP23126_Main_PSFB: 5Vp 12Vp C100 C101 C102 C103 C104 C105 C106 C107 C108 C224 C226 C242 C243 C244 CT100 CT200 D100 D101 J100 J101 J102 J103 J104 J105 J106 L100 L101 LEG1_HS LEG1_LS LEG2_HS LEG2_LS LOGO100 LOGO101 Logo102 Logo103 PGND Q215 Q216 Q217 Q218 Q219 R100 R101 R102 R103 R104 R105 R106 R107 R108 R109 SGND SGND101 SGND102 SGND103 T100 T101 T102 T103 TP100 TP101 TP103 TP104 TP105 TP106 TP107 TP108 TP109 TP110 TP111 TP112 TP113 TP114 TP217 TP218 TP219 TP220 TP221 TP222 U100 Vin
component class PMP23126_Main_Controller: 5Vs 12Vs C200 C201 C202 C203 C205 C210 C211 C212 C213 C214 C215 C216 C217 C218 C219 D200 D201 D202 D203 J200 J201 J202 J300 J305 J306 L200 PSON R200 R201 R202 R203 R204 R205 R206 R207 R208 R209 R210 R211 R212 R213 R220 R221 R222 R223 R224 R225 R226 R227 R228 R229 R230 R231 R232 R233 R234 R235 R305 R323 R329 R331 R333 R334 R335 R337 RT200 SGND U201 U202 U203
net class HV: SWNODE1 SWNODE1_1 SWNODE2 SWNODE2_1 VBB
component class Output_Decoupling: C300 C301 C302 C303 C304 C305 C306 C307 C308 C309 C310 C311 C312 C313 C314 C315 C316 C317 C318 C319 C320 C321 C322 C323 C324 C325 C326 C327 C328 C329 C330 C331 C332 C333 C334

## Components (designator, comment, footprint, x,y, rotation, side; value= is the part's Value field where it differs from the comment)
5Vp "5000" Keystone5000 3058,1364 r0 top
5Vs "5000" Keystone5000 3161,167 r90 top
12Vp "5000" Keystone5000 3430,1310 r0 top
12Vs "5000" Keystone5000 2761,167 r90 top
C100 "LGU2W221MELC" TS-UP_3500x3000 2037.4,1033.46 r180 top value=220uF
C101 "VJ1812Y104KXEAT5Z" 1812 5086,4432 r0 bottom value=0.1uF
C102 "CL31B223KHHNNNE" 1206 2600,2415 r180 top value=0.022uF
C103 "VJ1812Y104KXEAT5Z" 1812 1846,4427 r0 bottom value=0.1uF
C104 "CL31B223KHHNNNE" 1206 2600,3015 r180 top value=0.022uF
C105 "DE6E3KJ222MN3A" E_900x700x900 3745,3360 r270 bottom value=2200pF
C106 "C0805C105K3RACTU" 0805_HV 3344,1167 r270 top value=1uF
C107 "CL21A226KQQNNNE" 0805_HV 3176,1313 r0 top value=22uF
C108 "GCM31CR71C106KA64L" 1206_180 3443,1174 r270 top value=10uF
C200 "GRM155R70J103KA01D" 0402 4369.74,100.43 r180 top value=0.01uF
C201 "GRM155R70J103KA01D" 0402 4369.74,214.6 r180 top value=0.01uF
C202 "885012205044" 0402 5600,654 r0 top value=1000pF
C203 "GRM155R70J103KA01D" 0402 4700,650 r0 top value=0.01uF
C205 "CGA2B2X7R1H471K050BA" 0402 5557,276 r0 bottom value=470pF
C210 "06035A102KAT2A" 0603 5294.94,635.86 r90 bottom value=1000pF
C211 "C1608X7R1E105K080AB" 0603 5645.33,41.37 r0 top value=1uF
C212 "GRM1555C1E4R7CA01D" 0402 5802.81,139.8 r270 top value=4.7pF
C213 "04025U100CAT2A" 0402 5535.09,234.28 r0 top value=10pF
C214 "06035A102KAT2A" 0603 5366,671 r0 top value=1000pF
C215 "C0805C105K3RACTU" 0805_HV 2943.17,395.94 r270 top value=1uF
C216 "CL21A226KQQNNNE" 0805_HV 3093.17,325.94 r180 top value=22uF
C217 "GRM155R70J104KA01D" 0402 4814.62,175.23 r270 top value=0.1uF
C218 "GRM155R70J104KA01D" 0402 4672.89,53.18 r0 top value=0.1uF
C219 "GCM31CR71C106KA64L" 1206_180 2869.31,270.78 r0 top value=10uF
C300 "GRM31C5C1E104JA01L" 1206_180 4640,2500 r270 bottom value=0.1uF
C301 "GRM31C5C1E104JA01L" 1206_180 4720,2500 r270 bottom value=0.1uF
C302 "GRM31C5C1E104JA01L" 1206_180 4800,2500 r270 bottom value=0.1uF
C303 "GRM31C5C1E104JA01L" 1206_180 4880,2500 r270 bottom value=0.1uF
C304 "GRM31C5C1E104JA01L" 1206_180 4960,2500 r270 bottom value=0.1uF
C305 "C3216X5R1E476M160AC" 1206_190 5040,2500 r270 bottom value=47uF
C306 "C3216X5R1E476M160AC" 1206_190 5120,2500 r270 bottom value=47uF
C307 "C3216X5R1E476M160AC" 1206_190 4640,2720 r90 bottom value=47uF
C308 "C3216X5R1E476M160AC" 1206_190 4720,2720 r90 bottom value=47uF
C309 "C3216X5R1E476M160AC" 1206_190 4800,2720 r90 bottom value=47uF
C310 "APSG160ELL222MJ20S" FP-APSG160ELL222MJ20S_RADIAL-MFG 5705,1960 r0 top value=2.2mF
C311 "APSG160ELL222MJ20S" FP-APSG160ELL222MJ20S_RADIAL-MFG 5705,1530 r0 top value=2.2mF
C312 "APSG160ELL222MJ20S" FP-APSG160ELL222MJ20S_RADIAL-MFG 5335,1740 r180 top value=2.2mF
C313 "APSG160ELL222MJ20S" FP-APSG160ELL222MJ20S_RADIAL-MFG 5340,1315 r180 top value=2.2mF
C314 "APSG160ELL222MJ20S" FP-APSG160ELL222MJ20S_RADIAL-MFG 5710,1105 r0 top value=2.2mF
C315 "GRM31C5C1E104JA01L" 1206_180 4880,2720 r90 bottom value=0.1uF
C316 "GRM31C5C1E104JA01L" 1206_180 4960,2720 r90 bottom value=0.1uF
C317 "GRM31C5C1E104JA01L" 1206_180 5040,2720 r90 bottom value=0.1uF
C318 "GRM31C5C1E104JA01L" 1206_180 5120,2720 r90 bottom value=0.1uF
C319 "GRM31C5C1E104JA01L" 1206_180 5250,2160 r180 bottom value=0.1uF
C320 "C3216X5R1E476M160AC" 1206_190 5250,2240 r180 bottom value=47uF
C321 "C3216X5R1E476M160AC" 1206_190 5250,2320 r180 bottom value=47uF
C322 "C3216X5R1E476M160AC" 1206_190 5250,2400 r180 bottom value=47uF
C323 "C3216X5R1E476M160AC" 1206_190 5250,2480 r180 bottom value=47uF
C324 "C3216X5R1E476M160AC" 1206_190 5250,2720 r180 bottom value=47uF
C325 "GRM31C5C1E104JA01L" 1206_180 5250,2800 r180 bottom value=0.1uF
C326 "GRM31C5C1E104JA01L" 1206_180 5250,2880 r180 bottom value=0.1uF
C327 "GRM31C5C1E104JA01L" 1206_180 5180,2900 r180 top value=0.1uF
C328 "GRM31C5C1E104JA01L" 1206_180 5180,2820 r180 top value=0.1uF
C329 "GRM31C5C1E104JA01L" 1206_180 5180,2740 r180 top value=0.1uF
C330 "GRM31C5C1E104JA01L" 1206_180 5180,2660 r180 top value=0.1uF
C331 "GRM31C5C1E104JA01L" 1206_180 5180,2580 r180 top value=0.1uF
C332 "GRM31C5C1E104JA01L" 1206_180 5180,2500 r180 top value=0.1uF
C333 "GRM31C5C1E104JA01L" 1206_180 5180,2420 r180 top value=0.1uF
C334 "GRM31C5C1E104JA01L" 1206_180 5240,2140 r270 top value=0.1uF
CT100 "PAS6282NL" FP-PAS6282NL_PTH_12MM5_4MM5-MFG 4055.12,1801.18 r180 top value=3.3mH
D100 "B120-13-F" SMA 3605,1150 r270 top value=20V
D101 "B120-13-F" SMA 4465,1195 r0 bottom value=20V
D200 "BAS316,115" SOD-323 4968.17,592.55 r180 bottom value=100V
D201 "BAS316,115" SOD-323 4968.17,521.68 r180 bottom value=100V
D202 "BAS316,115" SOD-323 4987.85,379.95 r0 bottom value=100V
D203 "BAS316,115" SOD-323 4987.85,450.82 r0 bottom value=100V
J100 "M50-3000645" FP-M50-3000645_HDR12-MFG 3099,2185 r0 top
J101 "HLE-106-02-G-DV-BE-A" FP-HLE-106-02-G-DV-BE-A_HDR12-MFG 3291,4082 r180 bottom
J102 "575-4" Keystone_575-4 6996,2485 r0 top
J103 "PBC02DAAN" Sullins_PxC02DAAN 4710,1240 r270 top
J104 "575-4" Keystone_575-4 7010,885 r0 top
J105 "HLE-106-02-G-DV-BE-A" FP-HLE-106-02-G-DV-BE-A_HDR12-MFG 6541,4082 r180 bottom
J106 "PBC03DAAN" Sullins_PBC03DAAN 3970,1240 r270 top
J200 "HSEC8-160-01-L-DV-A-BL" controlCARD-120HSEC 4766.28,473.8 r180 top
J201 "GRPB102VWVN-RC" Sullins_GRPB102VWVN 4280,940 r180 top
J202 "GRPB102VWVN-RC" Sullins_GRPB102VWVN 4795,940 r180 top
L100 "PAL6567.421NL" FP-PAL6567.421NL_PTH_IND_34MM0_9MM5-MFG 5490,2860 r270 top value=0.42uH
L101 "74438336022" FP-74438336010_SMD2-MFG 3093,1167 r180 top
L200 "74438336022" FP-74438336010_SMD2-MFG 3198.17,450.94 r270 top
LEG1_HS "5004" Keystone5004 7145,4425 r90 top
LEG1_LS "5004" Keystone5004 7145,4570 r90 top
LEG2_HS "5004" Keystone5004 7145,4270 r90 top
LEG2_LS "5004" Keystone5004 7145,4060 r90 top
LOGO100 "CAUTION HOT SURFACE" IEC_HotSurface_Small 172,1504 r0 top
LOGO101 "DANGER HIGH VOLTAGE" IEC_HighVoltage_Small 159,1216 r0 top
Logo102 "FCC disclaimer" FCC_disclaimer 8811,7267 r90 top
Logo103 "WEEE logo" WEEE_Minimum 420,1200 r0 top
PGND "5001" Keystone5001 3440,1015 r90 top
PGND "5001" Keystone5001 3080,1015 r90 top
PGND "1715721" PhoenixContact_1715721 610,260 r0 top
PSON "5003" Keystone5003 3596,167 r90 top
R100 "CRCW0603243RFKEA" 0603 5491.79,746.09 r270 bottom value=243
R101 "CRCW0603243RFKEA" 0603 5578.4,746.09 r270 bottom value=243
R102 "RC1206FR-075K11L" 1206 5250,1970 r0 bottom value=5.11k
R103 "RC1206FR-075K11L" 1206 5250,2070 r0 bottom value=5.11k
R104 "CRCW06030000Z0EA" 0603 3225,2735 r90 bottom value=0
R105 "CRCW06030000Z0EA" 0603 3160,2735 r270 bottom value=0
R106 "CRCW06030000Z0EA" 0603 3225,3325 r90 bottom value=0
R107 "CRCW0402681KFKED" 0402 3119,1258 r180 bottom value=681k
R108 "CRCW06030000Z0EA" 0603 3165,3325 r270 bottom value=0
R109 "CRCW0402130KFKED" 0402 3244,1260 r180 bottom value=130k
R200 "CRCW04024K99FKED" 0402 4420.92,49.24 r0 top value=4.99k
R201 "CRCW0603100RFKEA" 0603 4487.85,108.3 r180 top value=100
R202 "CRCW04029K31FKED" 0402 4314.62,49.24 r0 top value=9.31k
R203 "CRCW04024K99FKED" 0402 4420.92,163.42 r0 top value=4.99k
R204 "CRCW0603100RFKEA" 0603 4487.85,218.54 r180 top value=100
R205 "ATC504L1000FTNCFT" 0402 5424.86,549.24 r180 bottom value=100
R206 "CRCW04020000Z0ED" 0402 5109.9,580.74 r0 bottom value=0
R207 "CRCW04029K31FKED" 0402 4314.62,163.42 r0 top value=9.31k
R208 "CRCW120614R7FKEA" 1206 5311,427 r90 bottom value=14.7
R209 "CRCW120614R7FKEA" 1206 5211,427 r90 bottom value=14.7
R210 "RC0603FR-079K76L" 0603 5078.4,490.19 r270 bottom value=9.76k
R211 "CRCW04021K40FKED" 0402 4680,715 r270 top value=1.40k
R212 "CRCW04020000Z0ED" 0402 5109.9,399.64 r0 bottom value=0
R213 "CRCW040210K0FKED" 0402 5447,277 r0 bottom value=10.0k
R220 "CRCW120637K4FKEA" 1206 5377.61,671.29 r90 bottom value=37.4k
R221 "CRCW0603100RFKEA" 0603 5389.43,801.21 r0 bottom value=100
R222 "RC0603FR-071K82L" 0603 5231.94,635.86 r270 bottom value=1.82k
R223 "RC0603FR-074R75L" 0603 5893.36,171.29 r180 top value=4.75
R224 "CRCW06032K49FKEA" 0603 5574.46,147.67 r90 top value=2.49k
R225 "CRCW120610K0FKEA" 1206 4365,360 r270 bottom value=10.0k
R226 "RC0603FR-074R75L" 0603 5893.36,108.3 r180 top value=4.75
R227 "CRCW06037K50FKEA" 0603 5511.47,147.67 r90 top value=7.50k
R228 "CRCW120637K4FKEA" 1206 5243,734 r90 top value=37.4k
R229 "CRCW0603100RFKEA" 0603 5369.5,799 r0 top value=100
R230 "CRCW0402681KFKED" 0402 3137.02,337.71 r0 bottom value=681k
R231 "RC0603FR-071K82L" 0603 5369,734 r180 top value=1.82k
R232 "CRCW0402130KFKED" 0402 3034.66,337.71 r0 bottom value=130k
R233 "CRCW04021K00FKED" 0402 4298.87,328.77 r270 bottom value=1.00k
R234 "CRCW120614R7FKEA" 1206 5411,427 r90 bottom value=14.7
R235 "CRCW120614R7FKEA" 1206 5511,427 r90 bottom value=14.7
RT200 "TMP6131DECR" DEC0002A 5556,238 r180 bottom
SGND "5001" Keystone5001 7382,4570 r90 top (schematic designator SGND100)
SGND "5001" Keystone5001 3756,167 r90 top
SGND "5001" Keystone5001 2961,167 r90 top
SGND "5001" Keystone5001 3361,167 r90 top
SGND101 "5001" Keystone5001 7382,4270 r90 top
SGND102 "5001" Keystone5001 7382,4120 r90 top
SGND103 "5001" Keystone5001 7382,4420 r90 top
T100 "CB70-14-CY" CB70-14-CY 6910,3573 r180 top
T101 "CB70-14-CY" CB70-14-CY 6913,3019 r180 top
T102 "CB70-14-CY" CB70-14-CY 6921,1936 r180 top
T103 "CB70-14-CY" CB70-14-CY 6916,1379 r180 top
TP100 "Suggest using a net name here" Mill-Max_0312-0-15-15-34-27-10-0 2185,3015 r180 top
TP101 "Suggest using a net name here" Mill-Max_0312-0-15-15-34-27-10-0 2160,2415 r180 top
TP103 "Suggest using a net name here" Mill-Max_0312-0-15-15-34-27-10-0 1441,4202 r0 top
TP104 "Suggest using a net name here" Mill-Max_0312-0-15-15-34-27-10-0 1241,4202 r0 top
TP105 "Suggest using a net name here" Mill-Max_0312-0-15-15-34-27-10-0 1741,4202 r0 top
TP106 "Suggest using a net name here" Mill-Max_0312-0-15-15-34-27-10-0 1941,4202 r0 top
TP107 "Suggest using a net name here" Mill-Max_0312-0-15-15-34-27-10-0 2441,4202 r0 top
TP108 "Suggest using a net name here" Mill-Max_0312-0-15-15-34-27-10-0 2241,4202 r0 top
TP109 "Suggest using a net name here" Mill-Max_0312-0-15-15-34-27-10-0 4491,4202 r0 top
TP110 "Suggest using a net name here" Mill-Max_0312-0-15-15-34-27-10-0 4691,4202 r0 top
TP111 "Suggest using a net name here" Mill-Max_0312-0-15-15-34-27-10-0 4991,4202 r0 top
TP112 "Suggest using a net name here" Mill-Max_0312-0-15-15-34-27-10-0 5191,4202 r0 top
TP113 "Suggest using a net name here" Mill-Max_0312-0-15-15-34-27-10-0 5491,4202 r0 top
TP114 "Suggest using a net name here" Mill-Max_0312-0-15-15-34-27-10-0 5691,4202 r0 top
U100 "TPS62160QDSGRQ1" DSG0008A 3244,1206.72 r180 top
U201 "TPS62160QDSGRQ1" DSG0008A 3048.17,425.94 r0 top
U202 "INA293B3IDBVR" DBV0005A_L 5704.39,139.8 r0 top
U203 "TLV71333PQDBVRQ1" DBV0005A_N 4704.39,151.61 r0 top
Vin "1715721" PhoenixContact_1715721 1330,260 r0 top

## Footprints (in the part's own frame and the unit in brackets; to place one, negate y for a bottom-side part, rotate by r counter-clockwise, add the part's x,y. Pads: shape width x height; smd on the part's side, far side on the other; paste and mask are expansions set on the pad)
0402 [mm] "0402 from SM-752 data"
  rect 0.8x0.6 smd: 1(-0.6,0) 2(0.6,0)
  silkscreen extent -1.22,-0.52 1.22,0.52, body extent -0.55,-0.3 0.55,0.3, height 0.6
0603 [mm] "0603 from SM-752 data"
  rect 1x0.95 smd: 1(-0.8,0) 2(0.8,0)
  silkscreen extent -1.52,-0.69 1.52,0.69, body extent -0.87,-0.47 0.87,0.47, height 1
0805_HV [mil] "0805 with 30mil clearance between pads"
  rect 50x63 smd: 1(-40,0) 2(40,0)
  silkscreen extent -74,-40 74,40, body extent -43,-29 43,29, height 57
1206 [mm] "1206 from SM-752 data"
  rect 1.3x1.85 smd: 1(-1.45,0) 2(1.45,0)
  silkscreen extent -2.4,-1.21 2.4,1.21, body extent -1.7,-0.9 1.7,0.9, height 1.35
1206_180 [mm] "1206_180"
  rect 1.1x1.6 smd: 1(-1.7,0) 2(1.7,0)
  silkscreen extent -0.9,-1 0.9,1, body extent -1.75,-0.95 1.75,0.95, height 1.8
1206_190 [mm] "1206_190"
  rect 1.1x1.6 smd: 1(-1.7,0) 2(1.7,0)
  silkscreen extent -0.9,-1 0.9,1, body extent -1.75,-0.95 1.75,0.95, height 1.9
1812 [mm]
  rect 1.6x3.4 smd: 1(-2,0) 2(2,0)
  silkscreen extent -0.8,-1.6 0.8,1.6, body extent -2.4,-1.7 2.4,1.7, height 1.35
CB70-14-CY [mil] "Terminal 90A Lug"
  rect 680x500 hole 254 copper offset -90,0 paste-250: 1(0,0)
  body extent -1300,-260 250,260, height 714
controlCARD-120HSEC [mm] "Pads are not numbered according to Samtec datasheet."
  rect 0.5x2.724 smd: 1(-23.357,-1.678) 2(-23.357,1.722) 3(-22.557,-1.678) 4(-22.557,1.722) 5(-21.757,-1.678) 6(-21.757,1.722) 7(-20.957,-1.678) 8(-20.957,1.722) 9(-20.157,-1.678) 10(-20.157,1.722) 11(-19.357,-1.678) 12(-19.357,1.722) 13(-18.557,-1.678) 14(-18.557,1.722) 15(-17.757,-1.678) 16(-17.757,1.722) 17(-16.957,-1.678) 18(-16.957,1.722) 19(-16.157,-1.678) 20(-16.157,1.722) 21(-15.357,-1.678) 22(-15.357,1.722) 23(-14.557,-1.678) 24(-14.557,1.722) 25(-13.757,-1.678) 26(-13.757,1.722) 27(-12.957,-1.678) 28(-12.957,1.722) 29(-12.157,-1.678) 30(-12.157,1.722) 31(-11.357,-1.678) 32(-11.357,1.722) 33(-10.557,-1.678) 34(-10.557,1.722) 35(-9.757,-1.678) 36(-9.757,1.722) 37(-8.957,-1.678) 38(-8.957,1.722) 39(-8.157,-1.678) 40(-8.157,1.722) 41(-7.357,-1.678) 42(-7.357,1.722) 43(-6.557,-1.678) 44(-6.557,1.722) 45(-5.757,-1.678) 46(-5.757,1.722) 47(-4.957,-1.678) 48(-4.957,1.722) 49(-4.157,-1.678) 50(-4.157,1.722) 51(-3.357,-1.678) 52(-3.357,1.722) 53(-2.557,-1.678) 54(-2.557,1.722) 55(-1.757,-1.678) 56(-1.757,1.722) 57(2.243,-1.678) 58(2.243,1.722) 59(3.043,-1.678) 60(3.043,1.722) 61(3.843,-1.678) 62(3.843,1.722) 63(4.643,-1.678) 64(4.643,1.722) 65(5.443,-1.678) 66(5.443,1.722) 67(6.243,-1.678) 68(6.243,1.722) 69(7.043,-1.678) 70(7.043,1.722) 71(7.843,-1.678) 72(7.843,1.722) 73(8.643,-1.678) 74(8.643,1.722) 75(9.443,-1.678) 76(9.443,1.722) 77(10.243,-1.678) 78(10.243,1.722) 79(11.043,-1.678) 80(11.043,1.722) 81(11.843,-1.678) 82(11.843,1.722) 83(12.643,-1.678) 84(12.643,1.722) 85(13.443,-1.678) 86(13.443,1.722) 87(14.243,-1.678) 88(14.243,1.722) 89(15.043,-1.678) 90(15.043,1.722) 91(15.843,-1.678) 92(15.843,1.722) 93(16.643,-1.678) 94(16.643,1.722) 95(17.443,-1.678) 96(17.443,1.722) 97(18.243,-1.678) 98(18.243,1.722) 99(19.043,-1.678) 100(19.043,1.722) 101(19.843,-1.678) 102(19.843,1.722) 103(20.643,-1.678) 104(20.643,1.722) 105(21.443,-1.678) 106(21.443,1.722) 107(22.243,-1.678) 108(22.243,1.722) 109(23.043,-1.678) 110(23.043,1.722) 111(23.843,-1.678) 112(23.843,1.722) 113(24.643,-1.678) 114(24.643,1.722) 115(25.443,-1.678) 116(25.443,1.722) 117(26.243,-1.678) 118(26.243,1.722) 119(27.043,-1.678) 120(27.043,1.722)
  round 0.025 hole 1.27 unplated mask+0.876: 181(-24.857,0.022) 182(28.543,1.522)
  round 1.348 hole 0.84: 185(-27.207,0.022) 186(30.893,0.022)
  silkscreen extent -32.11,-3.86 35.8,3.9, body extent -31.75,-3.48 35.3,3.52, height 12.35
DBV0005A_L [mm] "SOT23, 5-Leads, Body 2.9x1.6mm, Pitch 0.95mm, Lead Span 2.8mm, IPC High Density"
  rrect18% 0.8x0.55 smd: 1(-1.275,0.95) 2(-1.275,0) 3(-1.275,-0.95) 4(1.275,-0.95) 5(1.275,0.95)
  silkscreen extent -1.63,-1.55 0.38,1.55, body extent -1.42,-1.46 1.42,1.46, height 1.09
DBV0005A_N [mm] "SOT23, 5-Leads, Body 2.9x1.6mm, Pitch 0.95mm, Lead Span 2.8mm, IPC Medium Density"
  rrect17% 1x0.6 smd: 1(-1.375,0.95) 2(-1.375,0) 3(-1.375,-0.95) 4(1.375,-0.95) 5(1.375,0.95)
  silkscreen extent -1.63,-1.55 0.38,1.55, body extent -1.42,-1.46 1.42,1.46, height 1.09
DEC0002A [mm] "X1SON-2"
  rrect57% 0.35x0.6 smd paste-0.5 mask-0.05: 1(-0.325,0) 2(0.325,0)
  rrect33% 0.3x0.5 on Bottom Paste: 1S(-0.35,0) 2S(0.35,0)
  body extent -0.5,-0.3 0.5,0.3, height 0.5
DSG0008A [mm] "SON, 8-Leads, Body 2x2mm, Pitch 0.5mm, Thermal Pad 1.6x0.9mm, TI Recommended"
  rrect40% 0.5x0.25 smd: 1(-0.95,0.75) 2(-0.95,0.25) 3(-0.95,-0.25) 4(-0.95,-0.75) 5(0.95,-0.75) 6(0.95,-0.25) 7(0.95,0.25) 8(0.95,0.75)
  rrect14% 0.9x0.7 on Top Paste: 9(0,0.45) 9(0,-0.45)
  rrect11% 0.9x1.6 smd paste-0.45: 9(0,0)
  silkscreen extent -1.07,-1.15 1.07,1.15, body extent -1,-1 1,1, height 0.77
E_900x700x900 [mm] "TH, 2- Leads, Body 9x7mm, Pin Spacing 7.5mm"
  round 1.4 hole 0.9: 1(-3.75,0) 2(3.75,0)
  silkscreen extent -4.5,-3.5 4.5,3.5, body extent -4.5,-3.5 4.5,3.5, height 12
FCC_disclaimer [mil]
FP-74438336010_SMD2-MFG [mm]
  rrect8% 1.3x3.4 smd paste+0 mask+0: 1(-1.05,0) 2(1.05,0)
  silkscreen extent -1.6,-2.1 1.6,2.1, body extent -1.5,-1.5 1.5,1.5, height 2
FP-APSG160ELL222MJ20S_RADIAL-MFG [mm]
  round 1.25 hole 0.75 paste-1000 mask+0: 1(-2.5,0)
  rect 1.25x1.25 hole 0.75 paste-1000 mask+0: 2(2.5,0)
  silkscreen extent -5.25,-5.25 5.25,5.25, body extent -5.35,-5.35 5.35,5.35, height 0.25
FP-HLE-106-02-G-DV-BE-A_HDR12-MFG [mm]
  rrect8% 1.27x1.68 smd paste+0 mask+0: 1(6.35,-2.72) 2(6.35,2.72) 3(3.81,-2.72) 4(3.81,2.72) 5(1.27,-2.72) 6(1.27,2.72) 7(-1.27,-2.72) 8(-1.27,2.72) 9(-3.81,-2.72) 10(-3.81,2.72) 11(-6.35,-2.72) 12(-6.35,2.72)
  round 0.97 hole 0.97 unplated paste-1000 mask+0: ""(-6.35,-1.27) ""(-6.35,1.27) ""(-3.81,-1.27) ""(-3.81,1.27) ""(-1.27,-1.27) ""(-1.27,1.27) ""(1.27,-1.27) ""(1.27,1.27) ""(3.81,-1.27) ""(3.81,1.27) ""(6.35,-1.27) ""(6.35,1.27)
  round 1.78 hole 1.78 unplated paste-1000 mask+0: ""(-5.08,0) ""(5.08,0)
  silkscreen extent -7.72,-4.4 7.72,2.61, body extent -7.62,-3.29 7.62,3.29, height 3.79
FP-M50-3000645_HDR12-MFG [mm]
  rrect9% 1.12x1.12 hole 0.7 paste-1000 mask+0: 1(-3.175,-0.635)
  round 1.12 hole 0.7 paste-1000 mask+0: 2(-3.175,0.635) 3(-1.905,-0.635) 4(-1.905,0.635) 5(-0.635,-0.635) 6(-0.635,0.635) 7(0.635,-0.635) 8(0.635,0.635) 9(1.905,-0.635) 10(1.905,0.635) 11(3.175,-0.635) 12(3.175,0.635)
  silkscreen extent -4.73,-1.63 4.16,1.63, body extent -4.26,-1.73 4.26,1.73, height 0.25
FP-PAL6567.421NL_PTH_IND_34MM0_9MM5-MFG [mm]
  rrect2% 11.6x4.1 hole 3.5 slot 11 at 0 deg paste-1000 mask+0: 1(-11.45,0)
  rrect100% 11.6x4.1 hole 3.5 slot 11 at 0 deg paste-1000 mask+0: 2(11.45,0)
  silkscreen extent -18.01,-4.75 17,4.75, body extent -17.35,-4.85 17.35,4.85, height 0.25
FP-PAS6282NL_PTH_12MM5_4MM5-MFG [mm]
  rrect5% 1.85x1.85 hole 1.2 paste-1000 mask+0: 1(5,1)
  round 1.85 hole 1.2 paste-1000 mask+0: 2(-5,1) 3(-5,-1) 4(5,-1)
  silkscreen extent -3.7,-2.25 5.12,2.87, body extent -6.35,-2.35 6.35,2.35, height 0.25
IEC_HighVoltage_Small [mil]
  silkscreen extent -107,-88 107,97
IEC_HotSurface_Small [mil]
  silkscreen extent -107,-93 107,92
Keystone5000 [mil] "For Keystone 500x miniature loop terminals"
  round 80 hole 40: 1(0,0)
  silkscreen extent -52,-52 52,52, body extent -49,-49 49,49, height 182
Keystone5001 [mil] "For Keystone 500x miniature loop terminals"
  round 80 hole 40: 1(0,0)
  silkscreen extent -52,-52 52,52, body extent -49,-49 49,49, height 182
Keystone5003 [mil] "For Keystone 500x miniature loop terminals"
  round 80 hole 40: 1(0,0)
  silkscreen extent -52,-52 52,52, body extent -49,-49 49,49, height 182
Keystone5004 [mil] "For Keystone 500x miniature loop terminals"
  round 80 hole 40: 1(0,0)
  silkscreen extent -52,-52 52,52, body extent -49,-49 49,49, height 182
Keystone_575-4 [mm] "Banana Jack"
  round 10 hole 5.45: 1(0,0)
  body extent -3.95,-3.95 3.92,3.93, height 2.36
Mill-Max_0312-0-15-15-34-27-10-0 [mm] "Pin Receptacle, .032-.046\" .075\" Dia, Gold, TH"
  round 2.45 hole 1.905: 1(0,0)
  silkscreen extent -1.52,-1.52 1.52,1.52, body extent -1.15,-1.15 1.16,1.15, height 0.46
PhoenixContact_1715721 [mm] "Phoenix Contact 1715721 used on LM3445 design from Longmont"
  rrect5% 1.905x1.905 hole 1.3: 1(-2.54,0)
  round 1.9 hole 1.3: 2(2.54,0)
  silkscreen extent -5.82,-5.25 5.08,5.2, body extent -5.82,-4.6 5.08,5.2, height 14.2
SMA [mm] "Molded Diode, 2-Leads, Body 4.3x2.6mm, IPC Medium Density, based on OnSemi component dimensions and land pattern"
  rect 2x2 smd: 1(-2,0) 2(2,0)
  silkscreen extent -3.66,-1.57 2.79,1.57, body extent -2.6,-1.3 2.6,1.3, height 2.42
SOD-323 [mm] "NXP recommended land pattern"
  rect 0.6x0.6 smd paste-0.05: 1(-1.1,0) 2(1.1,0)
  silkscreen extent -2.06,-0.86 1.53,0.86, body extent -1.3,-0.67 1.3,0.68, height 1.1
Sullins_GRPB102VWVN [mm] "Header, 1.27mm, 10x2, TH"
  rrect50% 1.05x1.05 hole 0.7: 1(-5.715,0.635)
  round 1.05 hole 0.7: 2(-5.715,-0.635) 3(-4.445,0.635) 4(-4.445,-0.635) 5(-3.175,0.635) 6(-3.175,-0.635) 7(-1.905,0.635) 8(-1.905,-0.635) 9(-0.635,0.635) 10(-0.635,-0.635) 11(0.635,0.635) 12(0.635,-0.635) 13(1.905,0.635) 14(1.905,-0.635) 15(3.175,0.635) 16(3.175,-0.635) 17(4.445,0.635) 18(4.445,-0.635) 19(5.715,0.635) 20(5.715,-0.635)
  body extent -6.35,-1.7 6.35,1.7, height 4.15
Sullins_PBC03DAAN [mm] "Sullins 100mil, 2x3, 230 mil above insulator"
  rect 1.65x1.65 hole 1.016: 1(-1.27,2.54)
  round 1.65 hole 1.016: 2(1.27,2.54) 3(-1.27,0) 4(1.27,0) 5(-1.27,-2.54) 6(1.27,-2.54)
  silkscreen extent -2.67,-3.81 2.54,4.58, body extent -2.54,-3.81 2.54,3.81, height 8.38
Sullins_PxC02DAAN [mm] "Header, 2.54mm, 2x2, TH"
  rect 1.7x1.7 hole 1.2: 1(-1.27,1.27)
  round 1.7 hole 1.2: 2(1.27,1.27) 3(-1.27,-1.27) 4(1.27,-1.27)
  silkscreen extent -2.61,-2.8 2.61,3.2, body extent -2.61,-2.8 2.61,2.8, height 8.58
TS-UP_3500x3000 [mm] "PANASONIC"
  rect 2.8x2.8 hole 2: 1(-5,0)
  round 2.8 hole 2: 2(5,0)
  silkscreen extent -18,-18 18,18, body extent -17.86,-18 17.94,17.95, height 32.01
WEEE_Minimum [mil] "WEEElie bin"
  silkscreen extent -95,-172 99,104

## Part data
5Vp 5Vs 12Vp 12Vs: "Test Point, Miniature, Red, TH", Color=Red, Manufacturer=Keystone, Supplier Part Number 1=36-5000-ND
C100: library part ECOS2GP331EX, "CAP ALUM 220UF 20% 450V SNAP", Cap_Case=35x30mm, Manufacturer=Nichicon, Tolerance_%=20, Value2=450V, ValueDisplayed=220µF
C101 C103: "CAP, CERM, 0.1 µF, 500 V,+/- 10%, X7R, 1812", Cap_Case=1812, Manufacturer=Vishay-Vitramon, Supplier Part Number 1=720-1003-1-ND, TempCo=X7R, Tolerance_%=10, Value2=500V, ValueDisplayed=0.1µF
C102 C104: library part VJ1206Y223KXGAT5Z, "CAP, CERM, 0.022 µF, 630 V,+/- 10%, X7R, 1206", Cap_Case=1206, Manufacturer="Samsung Electro-Mechanics", TempCo=X7R, Tolerance_%=10, Value2=630V, ValueDisplayed=0.022µF
C105: "CAP, CERM, 2200 pF, 300 V, +/- 20%, E, TH, 2- Leads, Body 9x7mm, Pin Spacing 7.5mm", Cap_Case=9x7x9mm, Manufacturer=MuRata, Supplier Part Number 1=DE6E3KJ222MN3A-ND, TempCo=E, Tolerance_%=20, Value1=Unknown, Value2=300V, ValueDisplayed=2200pF
C106 C215: library part CMP-0007728-2, "CAP, CERM, 1 uF, 25 V, +/- 10%, X7R, 0805", Cap_Case=0805, Manufacturer=Kemet, Supplier Part Number 1=399-8004-1-ND, TempCo=X7R, Tolerance_%=10%, Value1=Unknown, Value2=25V, ValueDisplayed=1uF
C107 C216: library part CMP-0007989-2, "CAP, CERM, 22 uF, 6.3 V, +/- 10%, X5R, 0805", Cap_Case=0805, Manufacturer="Samsung Electro-Mechanics", TempCo=X5R, Tolerance_%=10%, Value1=Unknown, Value2=6.3V, ValueDisplayed=22uF
C108 C219: "CAP, CERM, 10 µF, 16 V,+/- 10%, X7R, AEC-Q200 Grade 1, 1206", Cap_Case=1206, Manufacturer=MuRata, Supplier Part Number 1=490-4793-1-ND, TempCo=X7R, Tolerance_%=10, Value2=16V, ValueDisplayed=10µF
C200 C201 C203: "CAP, CERM, 0.01uF, 6.3V, +/-10%, X7R, 0402", Cap_Case=0402, Manufacturer=MuRata, Supplier Part Number 1=GRM155R70J103KA01D-ND, TempCo=X7R, Tolerance_%=10, Value1=Unknown, Value2=6.3V, ValueDisplayed=0.01uF
C202: "CAP, CERM, 1000 pF, 25 V,+/- 10%, X7R, 0402", Cap_Case=0402, Manufacturer="Wurth Elektronik", Supplier Part Number 1=710-885012205044, TempCo=X7R, Tolerance_%=10, Value2=25V, ValueDisplayed=1000pF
